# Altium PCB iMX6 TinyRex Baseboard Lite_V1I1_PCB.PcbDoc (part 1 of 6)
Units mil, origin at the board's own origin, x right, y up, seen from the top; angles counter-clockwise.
Board outline 3149.61 x 3543.31 mil, 6 copper layers (L1, L2, L3, L4 (PWR), L5, L6), stack 60.634 mil thick; 385 components, 309 nets, 1566 pads, 914 vias.
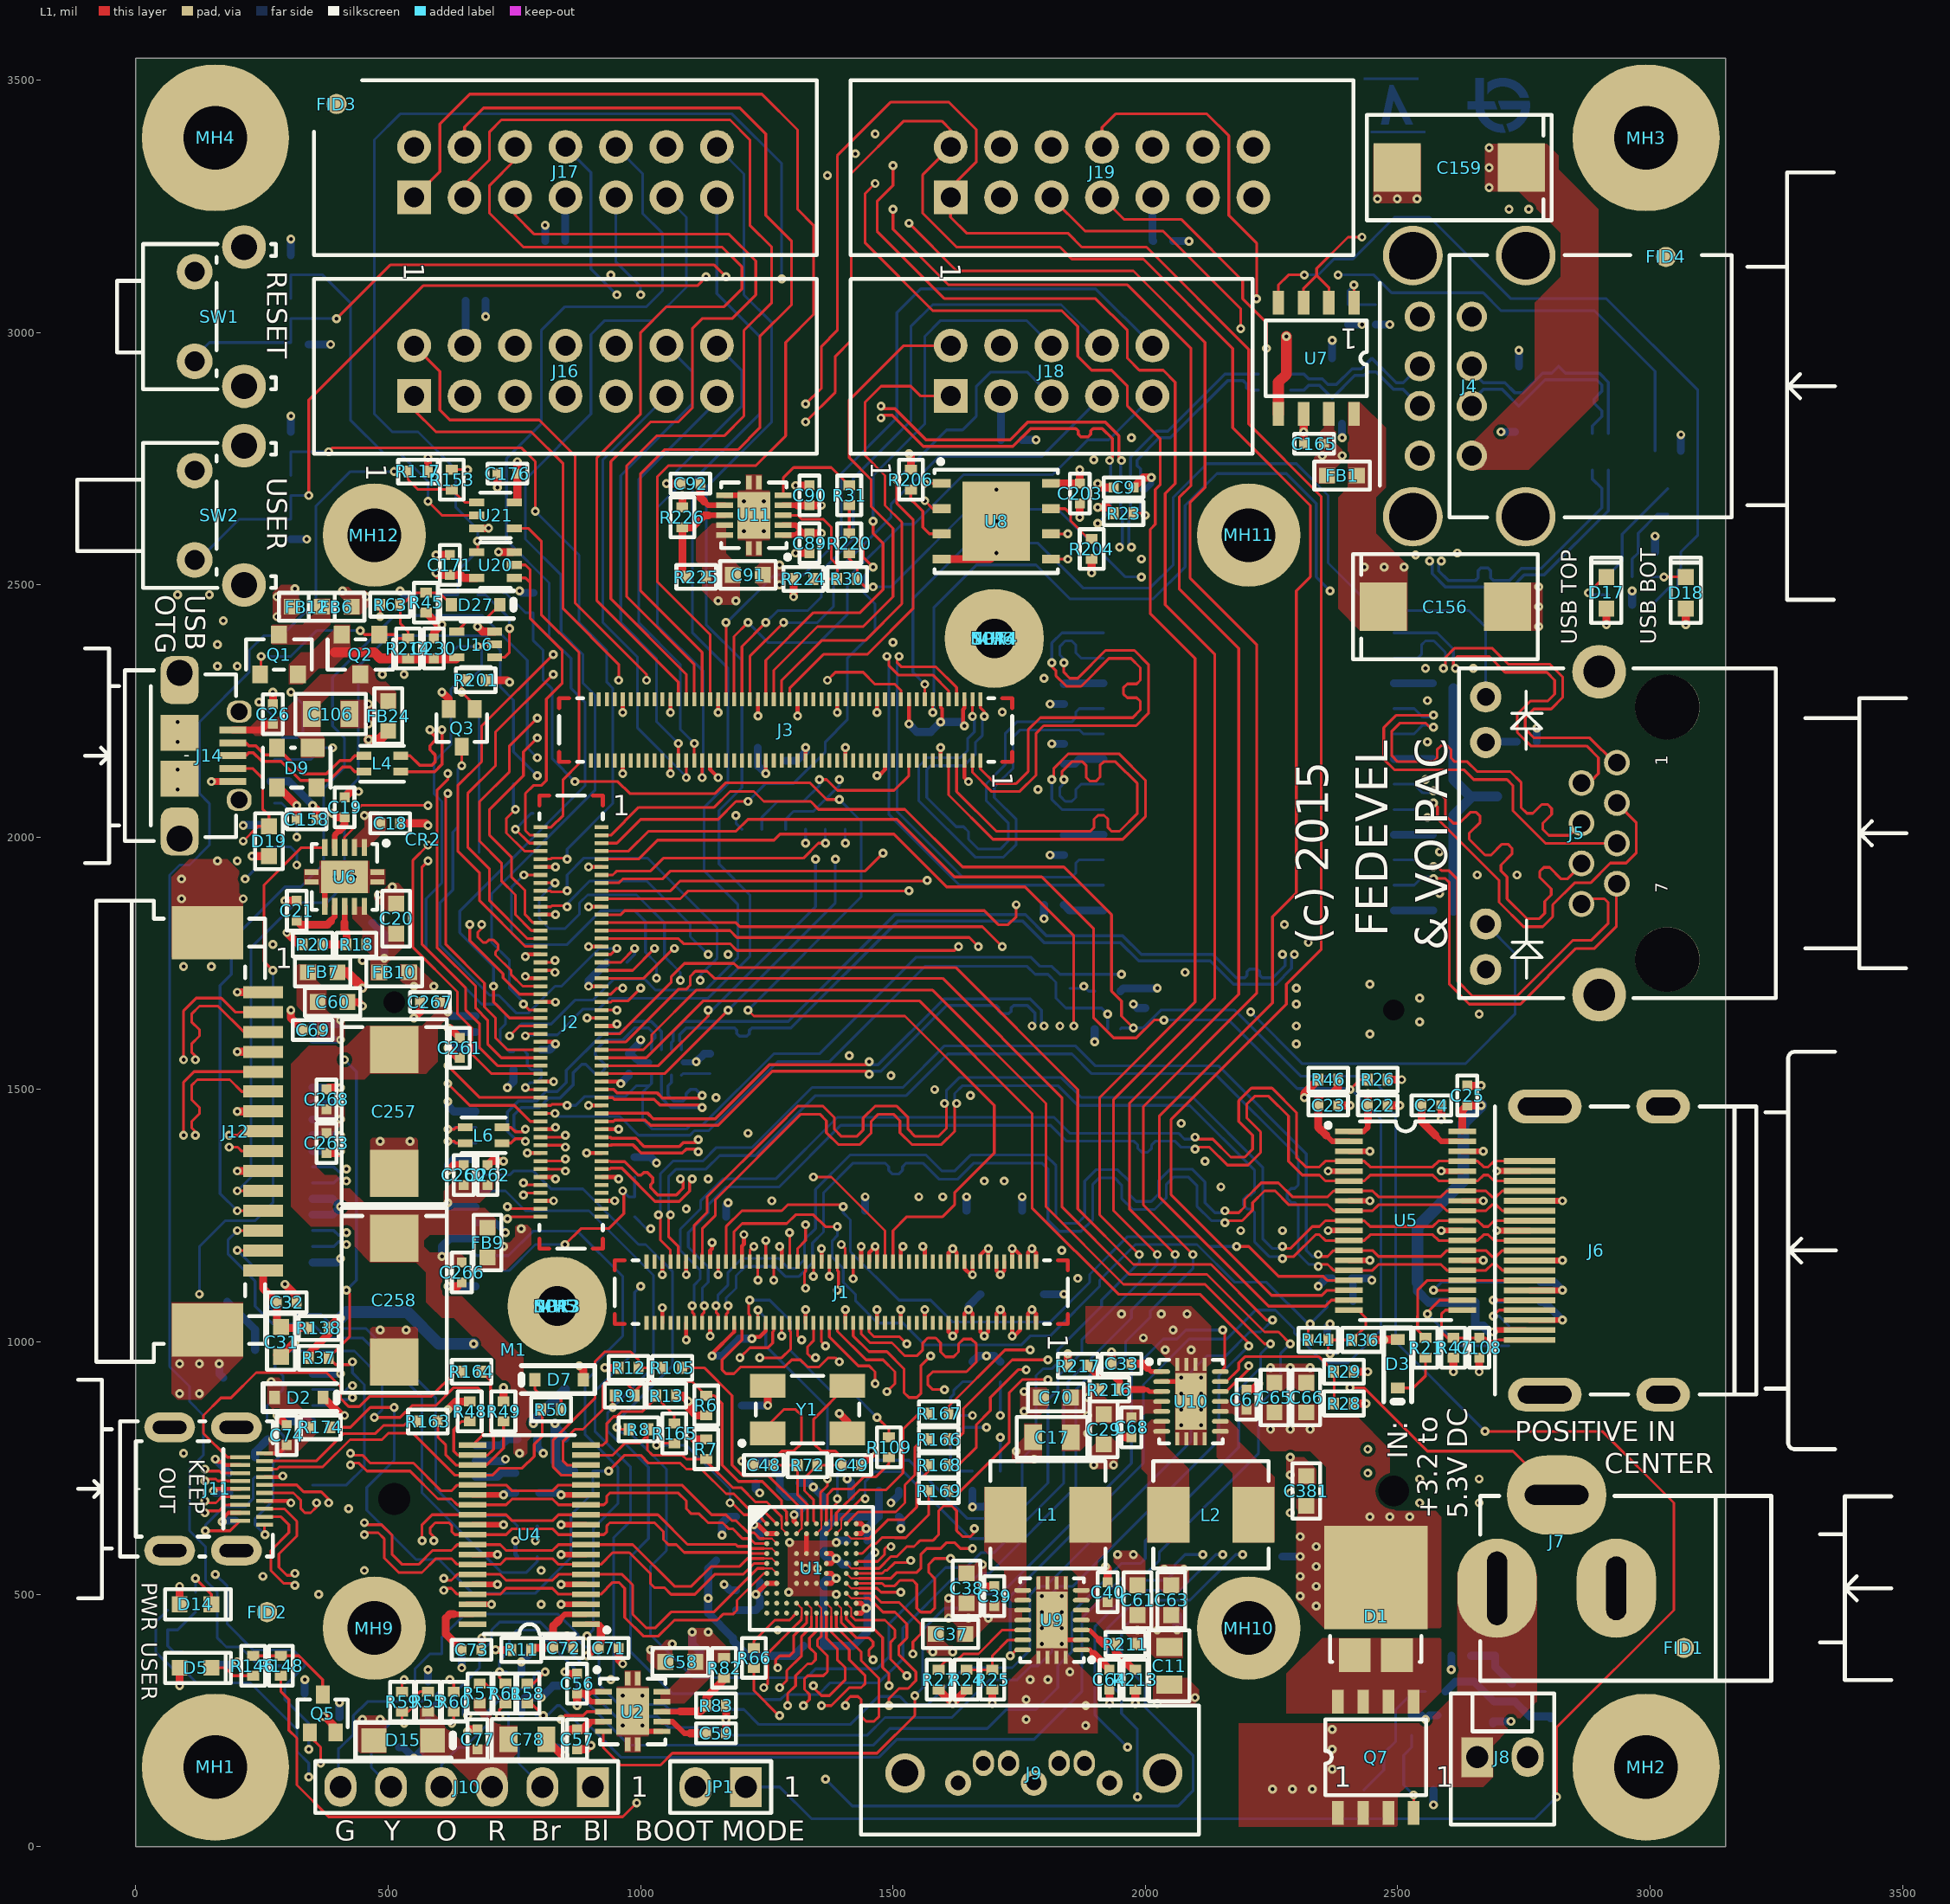
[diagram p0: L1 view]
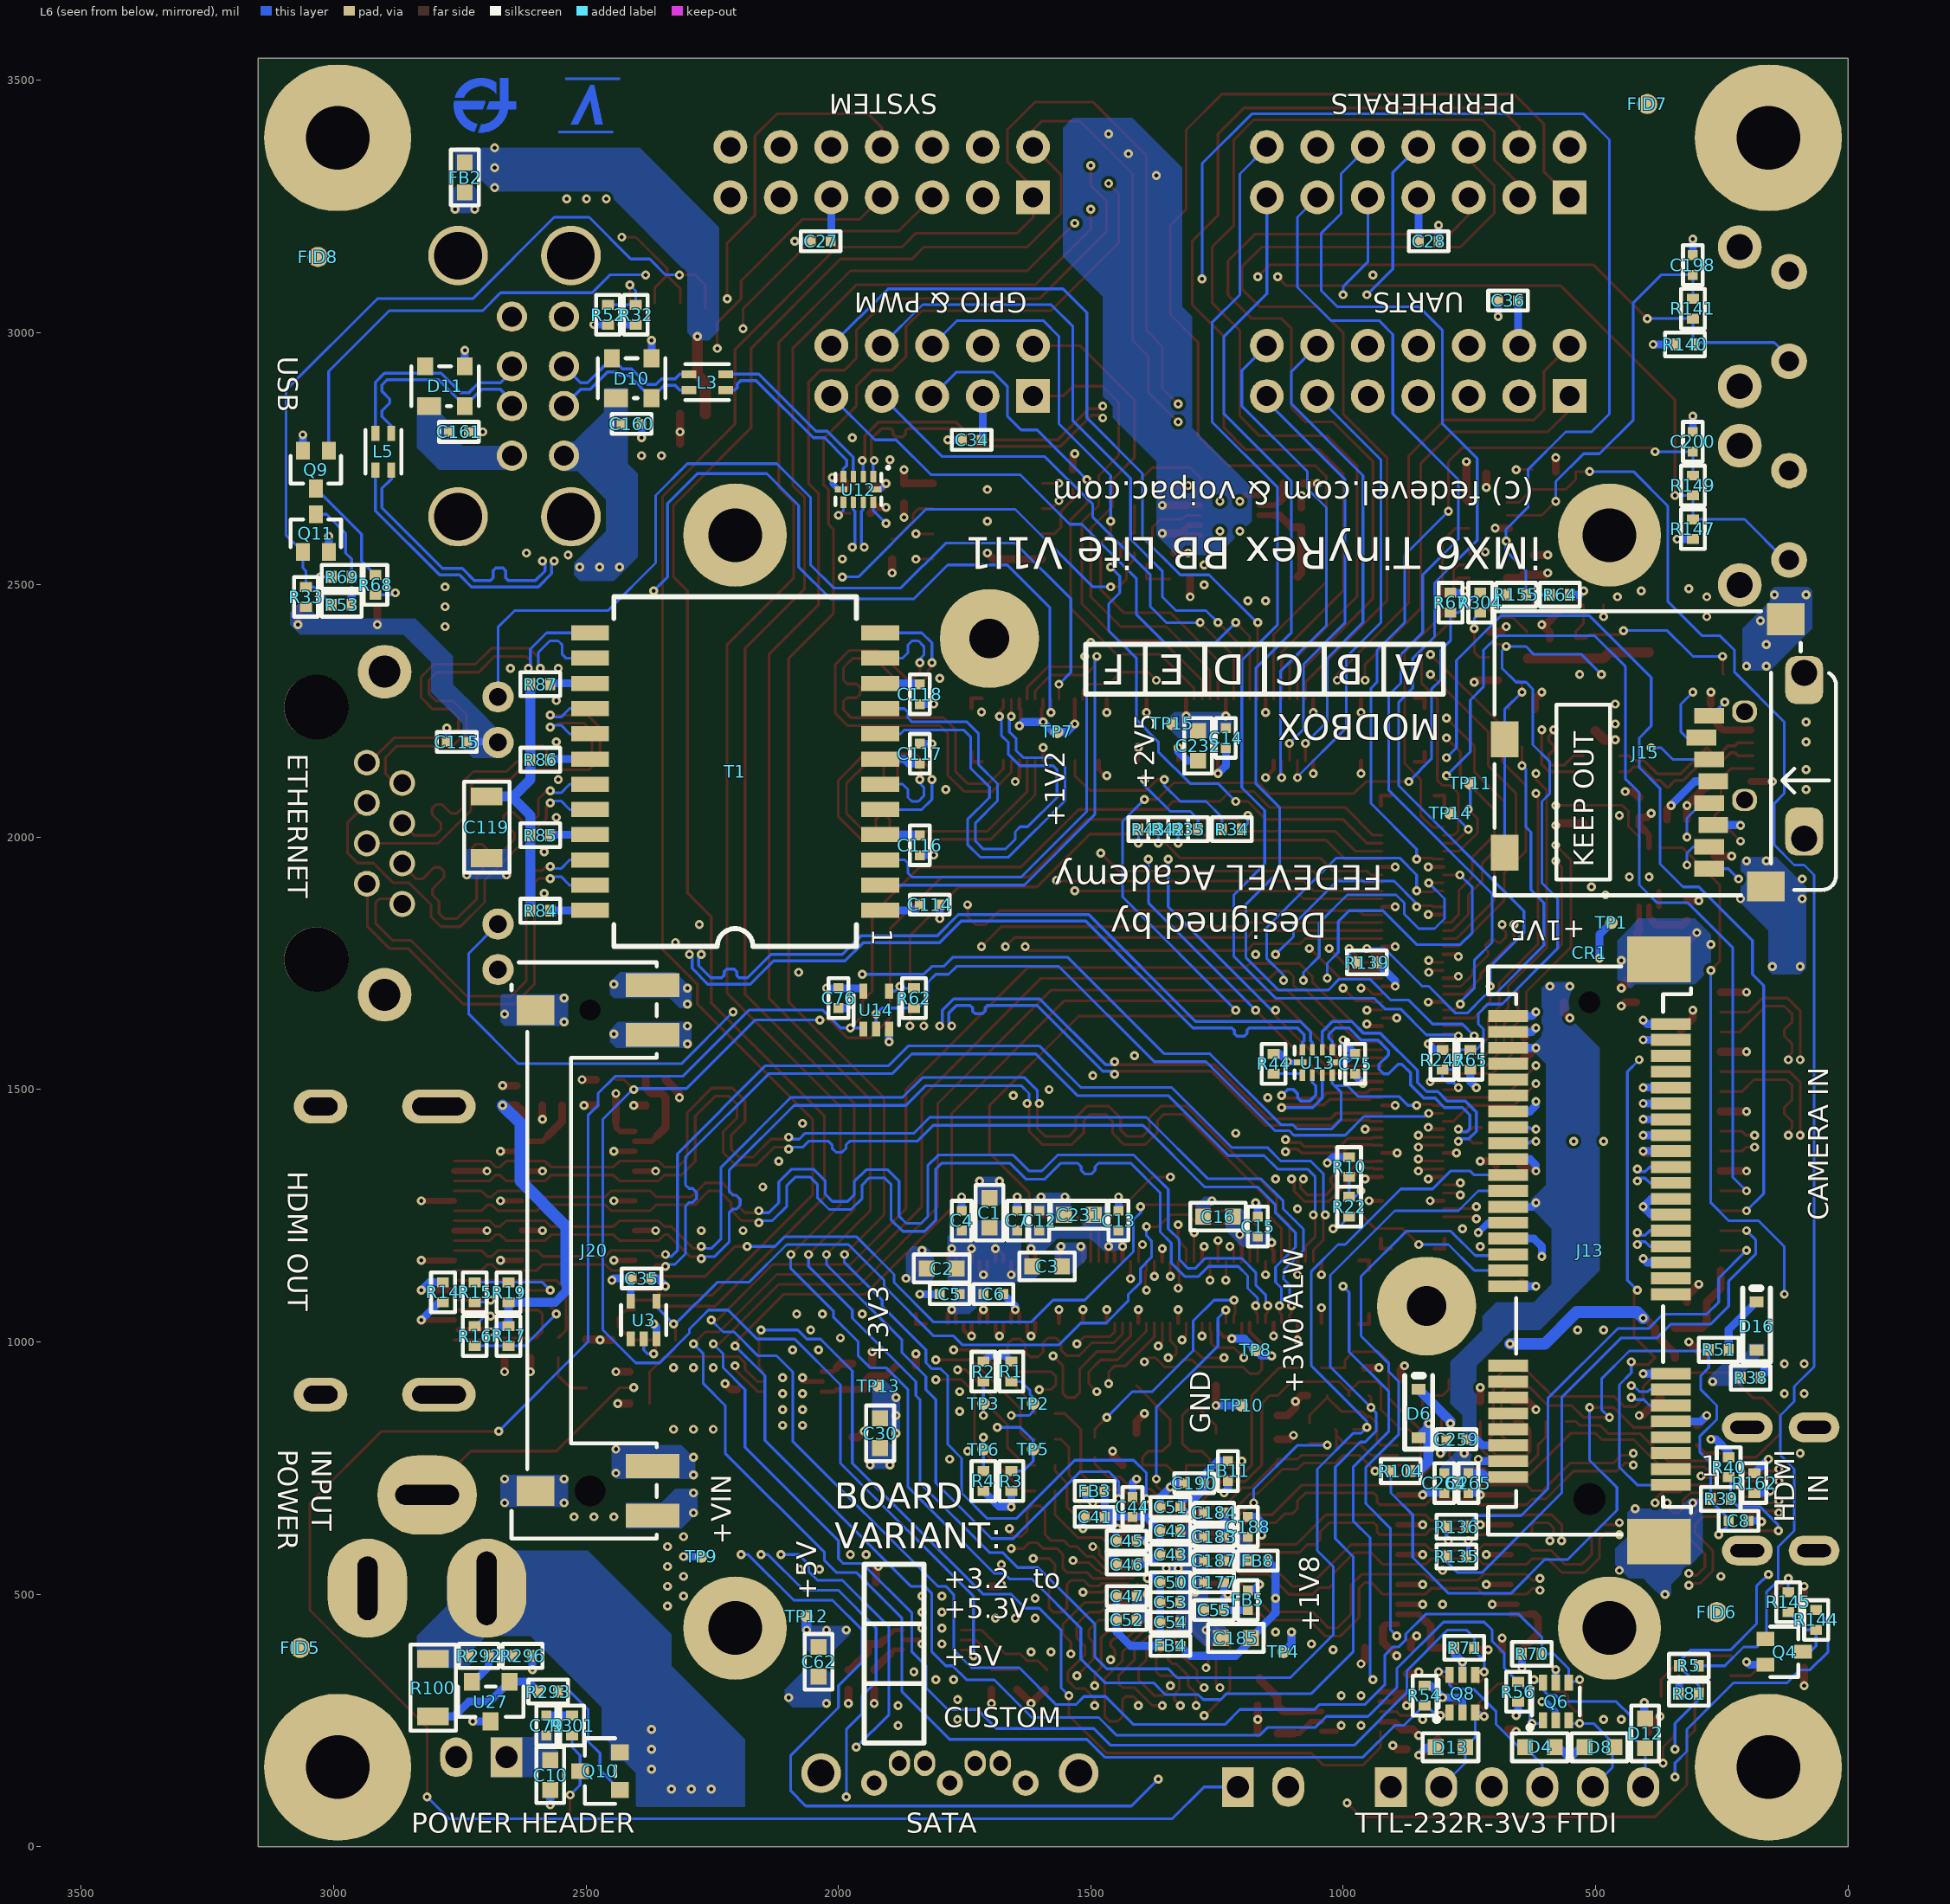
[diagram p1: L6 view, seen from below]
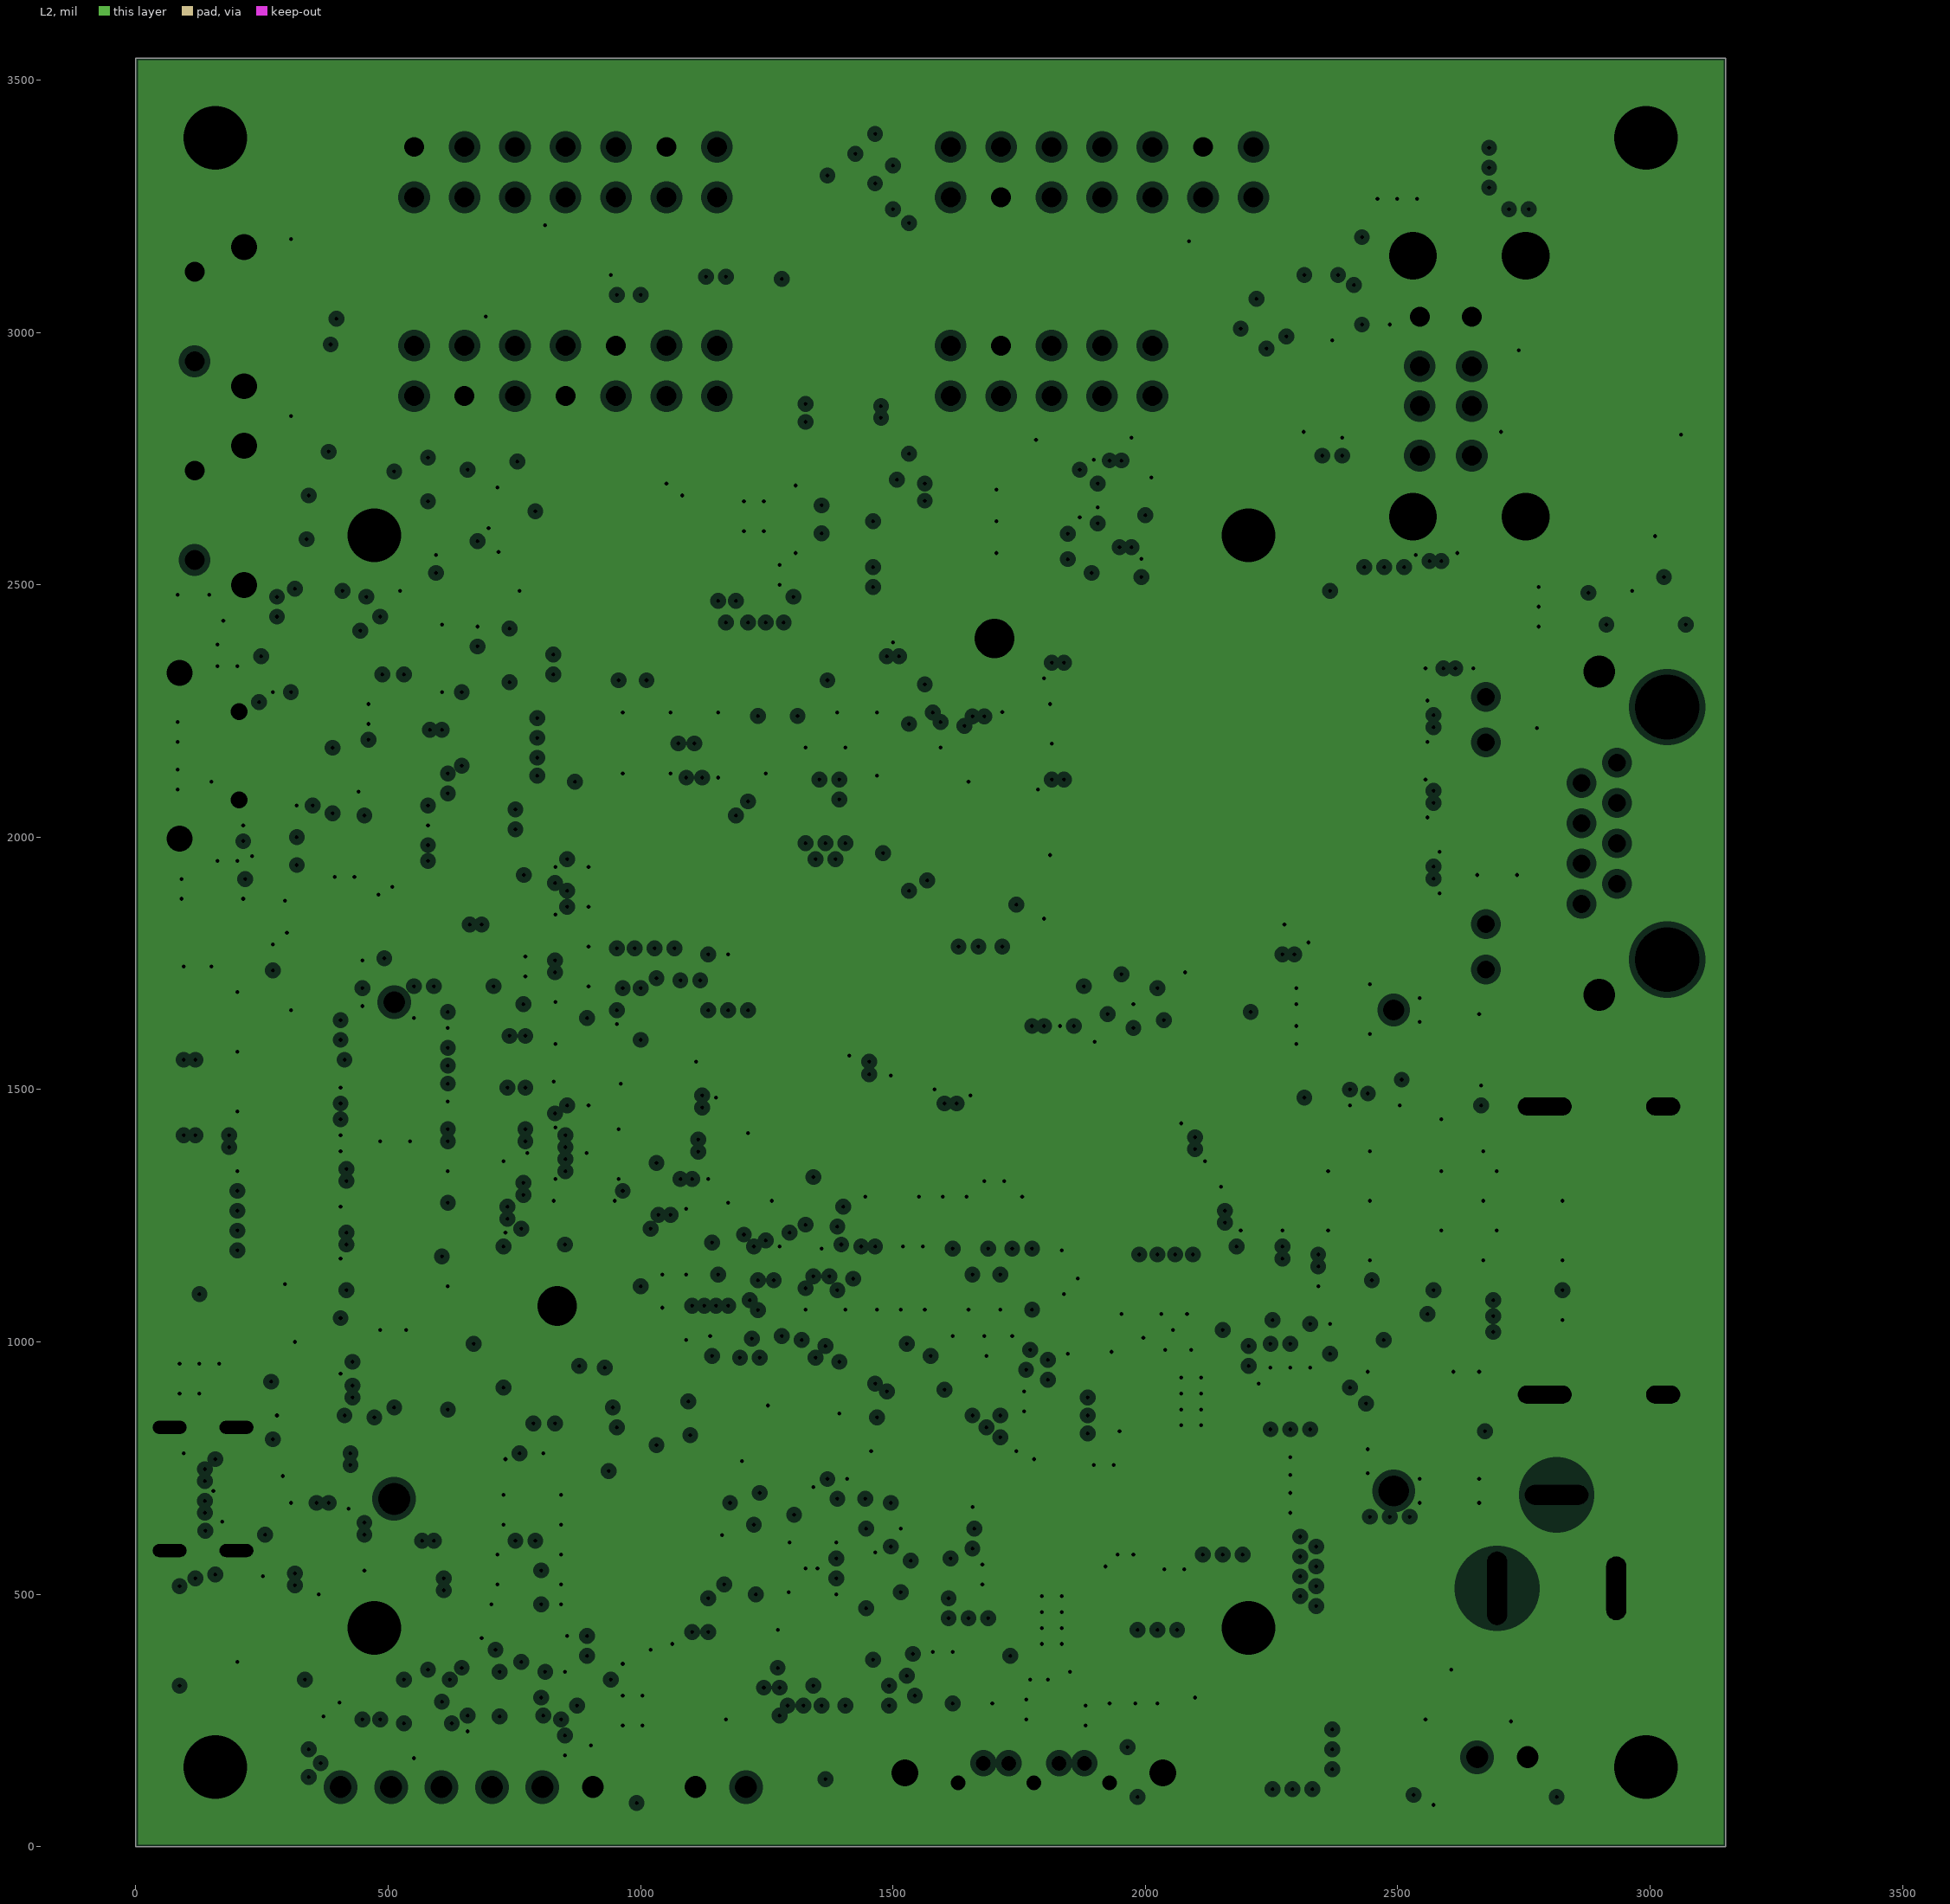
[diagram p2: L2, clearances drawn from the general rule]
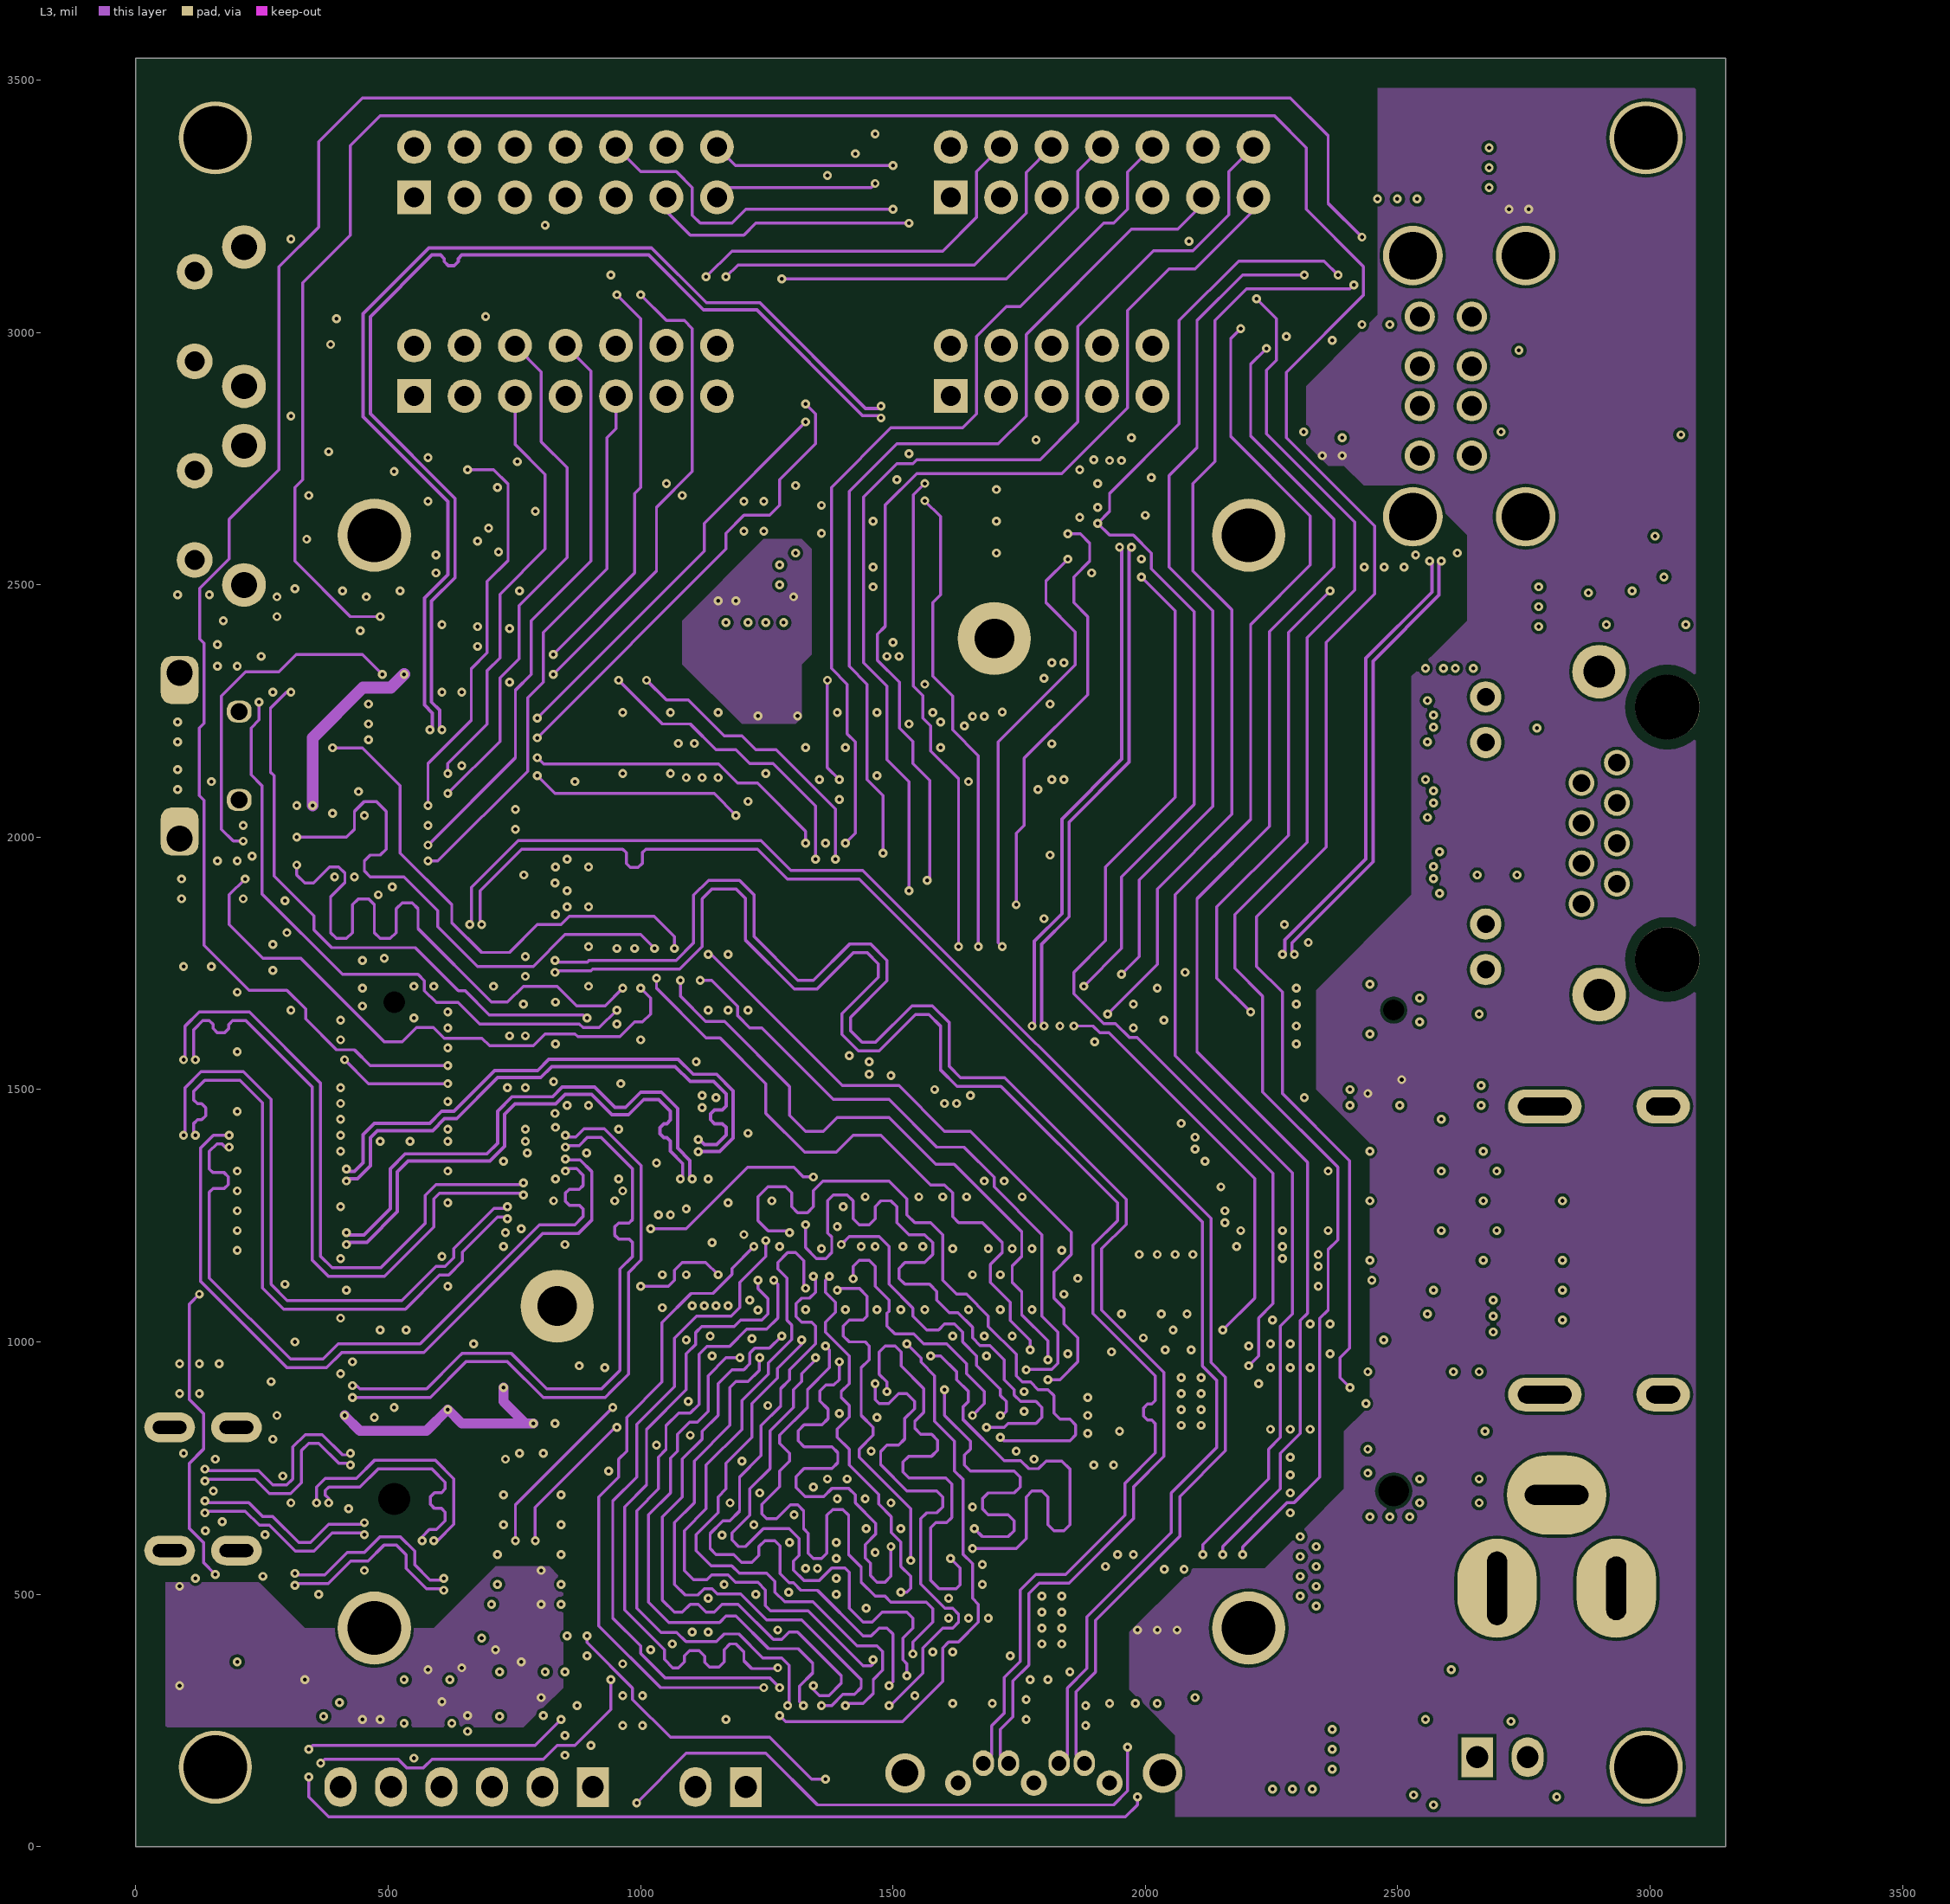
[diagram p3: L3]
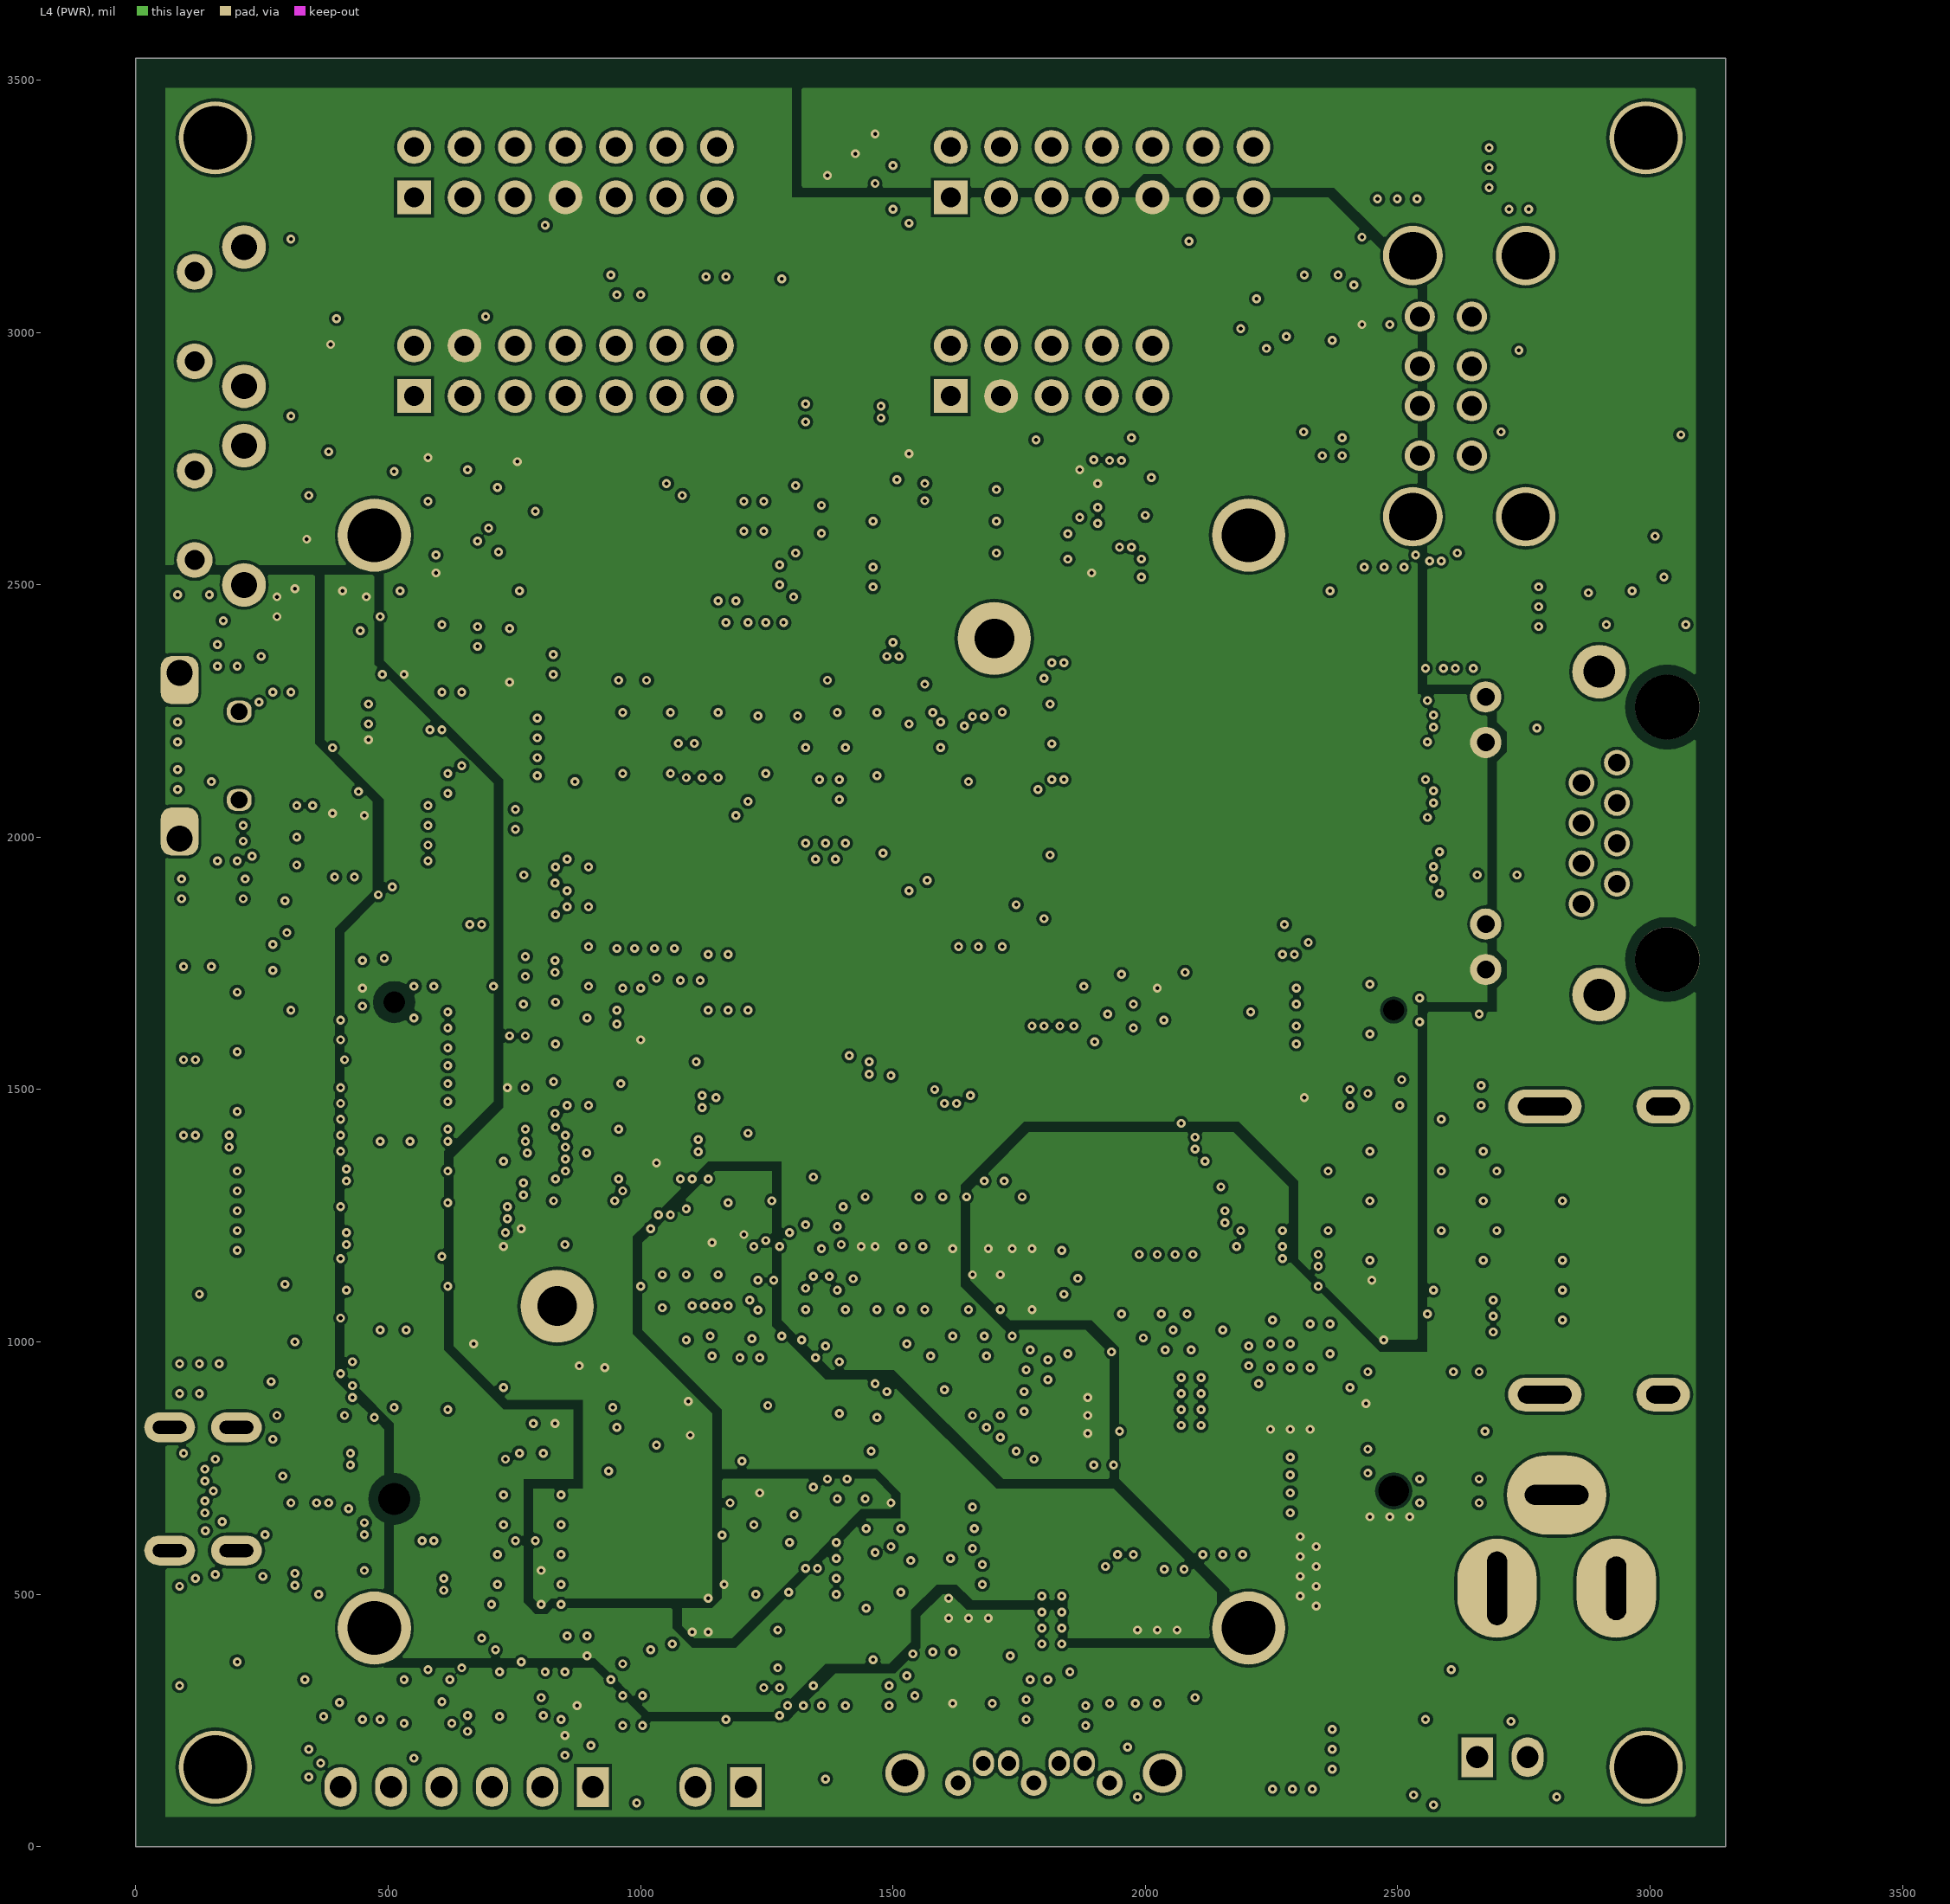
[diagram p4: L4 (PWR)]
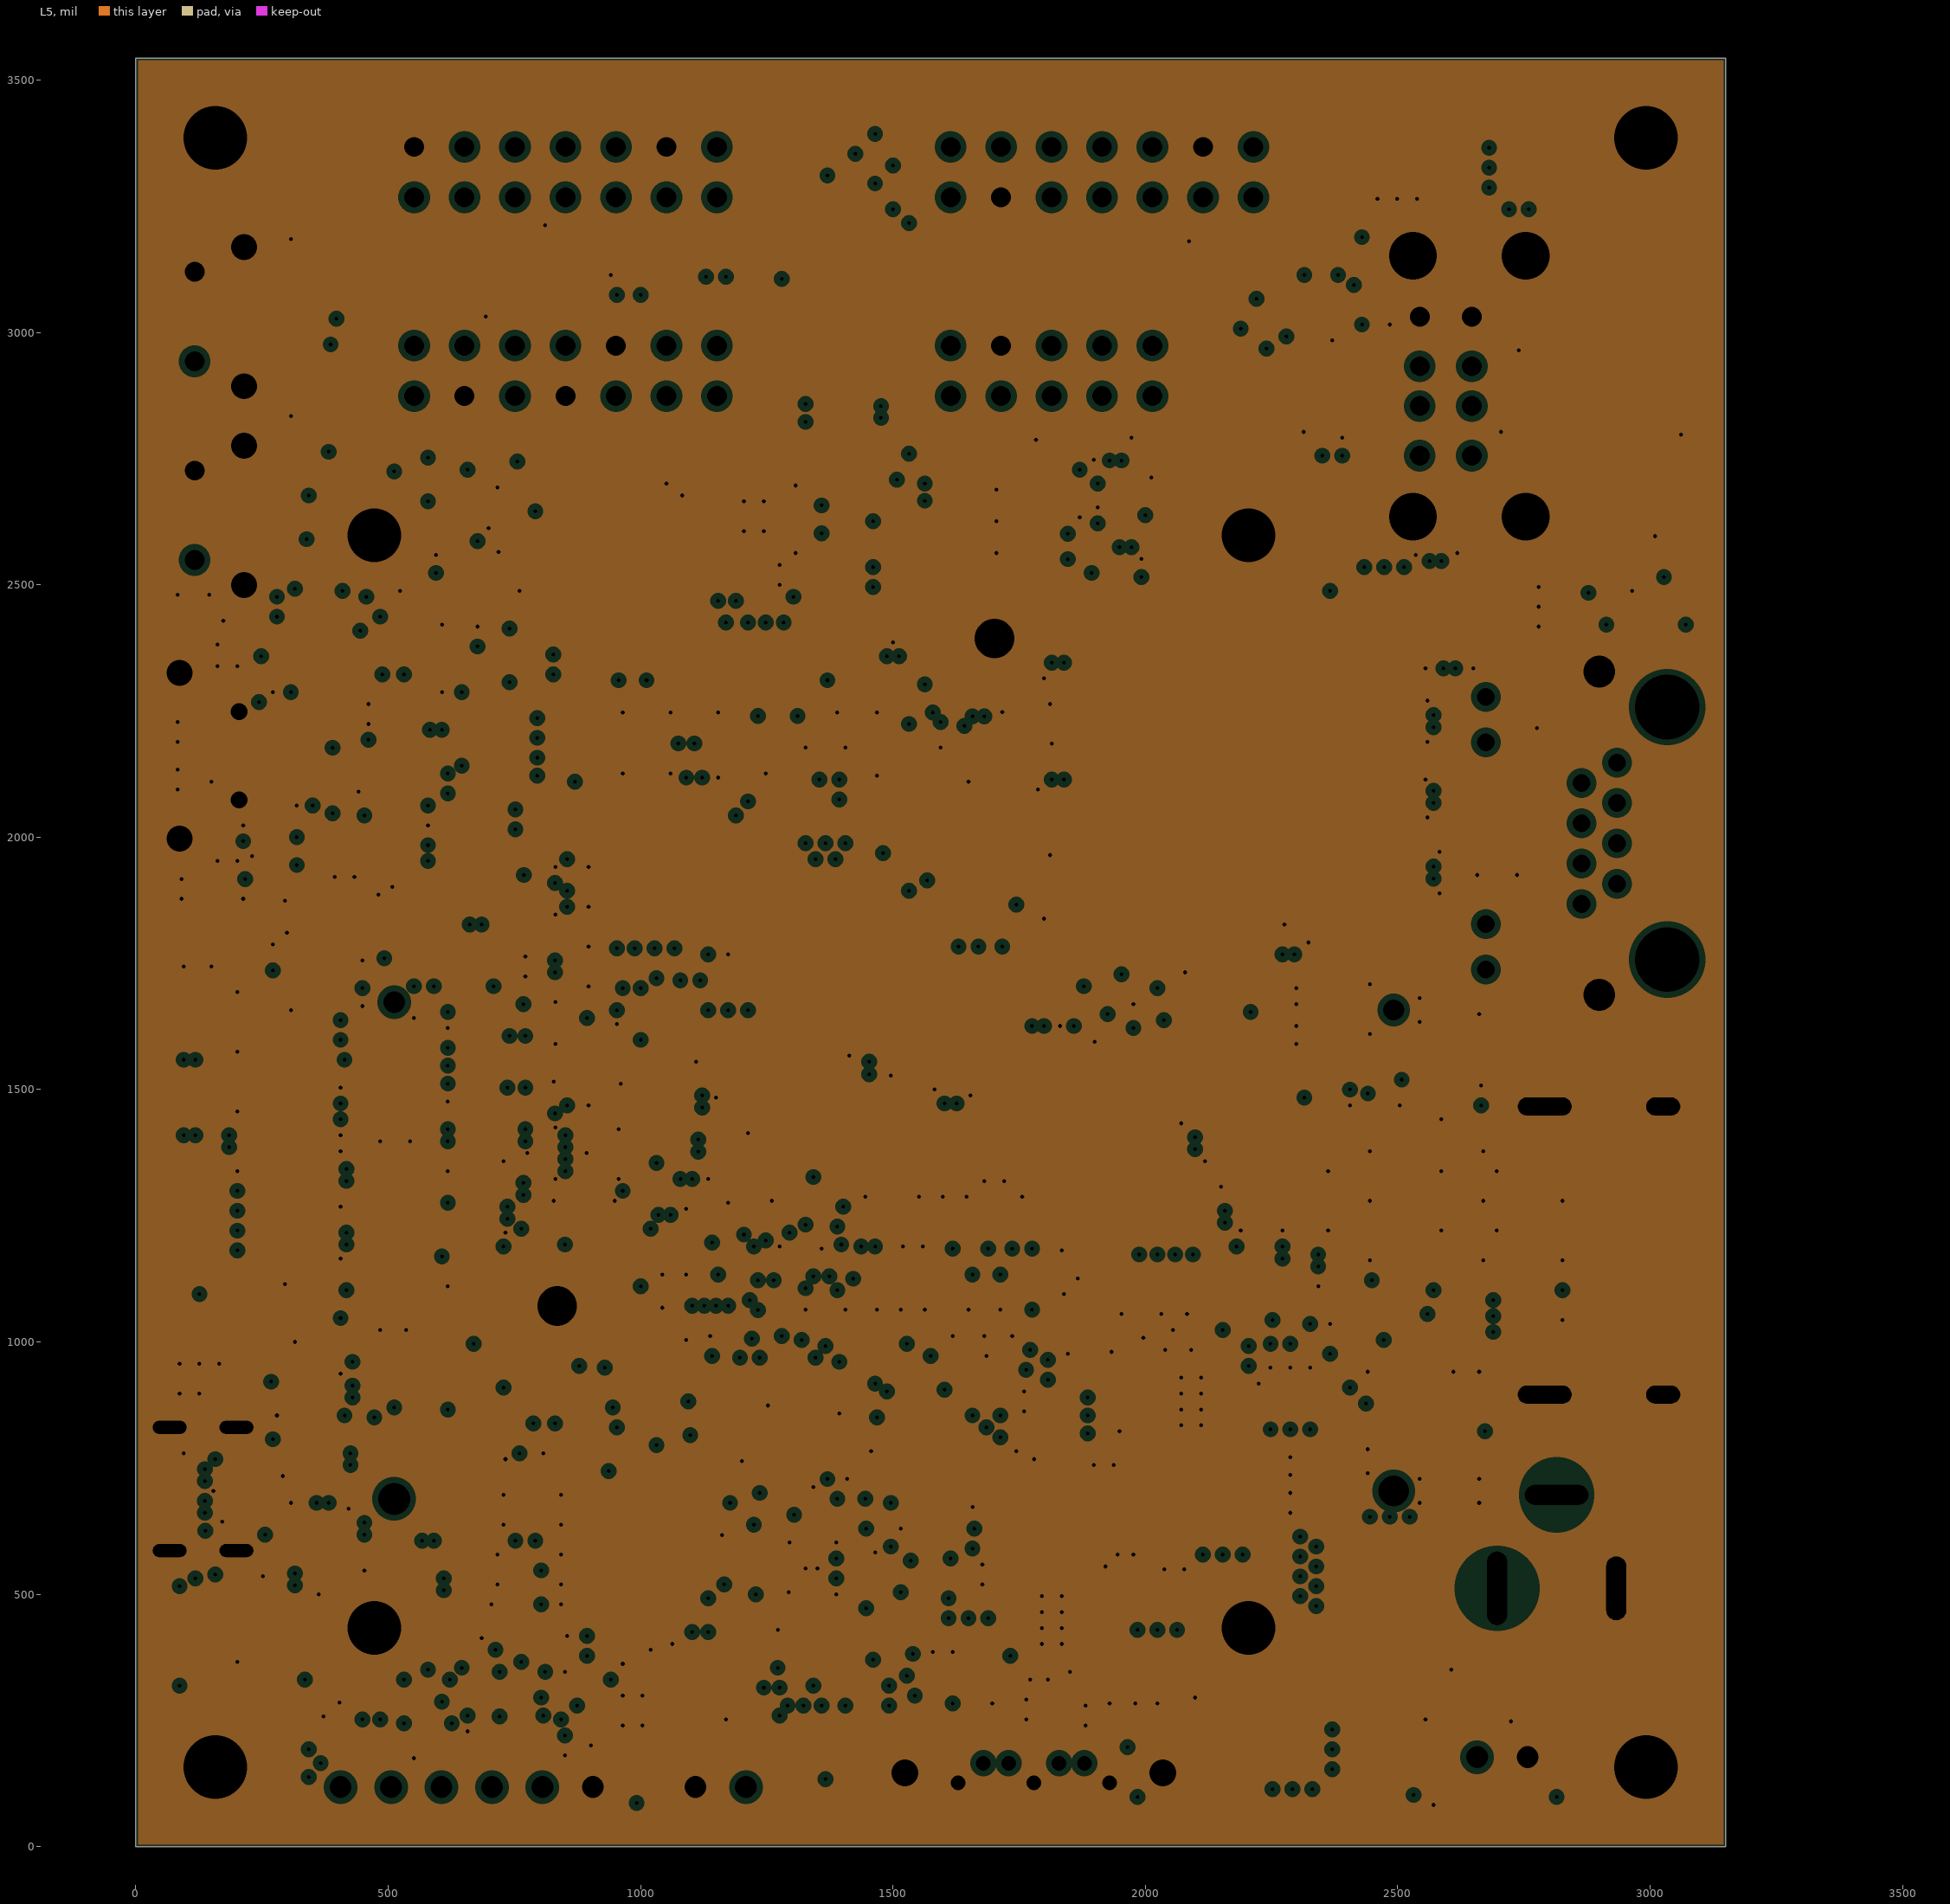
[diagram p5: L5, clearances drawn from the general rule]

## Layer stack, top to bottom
Top Solder: solder mask 0.4, Solder Resist, Dk 3.5
L1: signal copper 1.252
Dielectric1: core 4.64, DE 104 ML, Dk 4.3
L2: plane copper 0.685, net GND
Dielectric2: prepreg 5.5, DE 104 ML, Dk 3.95
L3: signal copper 0.685
Dielectric3: core 35.11, DE 104 ML, Dk 4.45
L4 (PWR): signal copper 0.685
Dielectric4: prepreg 5.5, DE 104 ML, Dk 3.95
L5: plane copper 0.685, net GND
Dielectric5: core 4.64, DE 104 ML, Dk 4.3
L6: signal copper 1.252
Bottom Solder: solder mask 0.4, Solder Resist, Dk 3.5

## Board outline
0,0 3149.61,0 3149.61,3543.31 0,3543.31 0,0

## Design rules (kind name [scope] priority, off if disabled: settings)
Clearance "Clearance Non Plated Holes" [InPadClass('NPTH')] p1: gap=19.68
Clearance "Pad Clearance" [IsPad vs IsPad] p2: gap=7.86
Clearance "CSI chip clearance" [WithinRoom('CSI') and OnLayer('L1')] p3: gap=2.95
Clearance "+VIN-L6 to GND pads" [InNamedPolygon('+VIN-L6') vs ispad] p4: gap=15.75
Clearance "Inners tracks" [IsTrack and (Layer = 'L3') and not(InNetClass('DIFF100') or InNetClass('DIFF90')) vs IsTrack] p5: gap=9.84
Clearance "Poly PWR to Via" [IsRegion AND OnLayer('L4 (PWR)') vs IsVia] p6: gap=5.91
Clearance "Poly to Poly" [IsRegion AND OnLayer('L4 (PWR)') vs IsRegion] p7: gap=15.75
Clearance [All] p8: gap=5.91
ComponentClearance "3D model Module" [InComponent('M1') vs InComponent('J1') or InComponent('J2') or InComponent('J3') or InComponent('SCR3') or InComponent('SCR4') or InComponent('SPA3') or InComponent('SPA4') or InComponent('NUT3') or InComponent('NUT4')] p1: gap=0 collisioncheckmode=3 verticalgap=0 showdistances=FALSE
ComponentClearance "MH5 to module mounting" [InComponent('MH5') vs InComponent('SCR3') or InComponent('SPA3')] p2: gap=0 collisioncheckmode=3 verticalgap=0 showdistances=FALSE
ComponentClearance "MH6 to module mounting" [InComponent('MH6') vs InComponent('SCR4') or InComponent('SPA4')] p3: gap=0 collisioncheckmode=3 verticalgap=0 showdistances=FALSE
ComponentClearance "SCR3 to module mounting" [InComponent('SCR3') vs InComponent('SPA3') or InComponent('NUT3')] p4: gap=0 collisioncheckmode=3 verticalgap=0 showdistances=FALSE
ComponentClearance "SCR4 to module mounting" [InComponent('SCR4') vs InComponent('SPA4') or InComponent('NUT4')] p5: gap=0 collisioncheckmode=3 verticalgap=0 showdistances=FALSE
ComponentClearance "PCIe card module to mounting" [InComponent('CR1') vs InComponent('J13') or InComponent('J20')] p6: gap=0 collisioncheckmode=3 verticalgap=0 showdistances=FALSE
ComponentClearance "SD Card model to SD slot" [InComponent('CR2') vs InComponent('J15')] p7: gap=0 collisioncheckmode=3 verticalgap=0 showdistances=FALSE
ComponentClearance "FID1 to J7" [InComponent('FID1') vs InComponent('J7')] p8: gap=0 collisioncheckmode=3 verticalgap=0 showdistances=FALSE
ComponentClearance "FID3 to J17" [InComponent('FID3') vs InComponent('J17')] p9: gap=0 collisioncheckmode=3 verticalgap=0 showdistances=FALSE
ComponentClearance "USB OTG power selection" [InComponent('FB12') vs InComponent('FB6')] p10: gap=0 collisioncheckmode=3 verticalgap=0 showdistances=FALSE
ComponentClearance "PIXCLOCK series resistors" [InComponent('R42') vs InComponent('R35') or InComponent('R43')] p11: gap=0 collisioncheckmode=3 verticalgap=0 showdistances=FALSE
ComponentClearance [All] p12: gap=7.87 collisioncheckmode=3 verticalgap=7.87 showdistances=FALSE
DiffPairsRouting DiffPair_DIFF100DiffPairsRouting [InDifferentialPairClass('DIFF100')] p1: maxlimit=11.09 minlimit=10 mostfreqgap=11.09 toplayer_mingap=10.51 toplayer_maxgap=10.51 toplayer_prefgap=10.51 toplayer_minwidth=3.94 toplayer_maxwidth=5.4 toplayer_prefwidth=5.4 midlayer1_mingap=11.09 midlayer1_minwidth=6 midlayer1_maxwidth=6 midlayer1_prefwidth=6 midlayer2_maxgap=10 midlayer2_prefgap=10 midlayer2_minwidth=10 midlayer2_maxwidth=10 midlayer2_prefwidth=10 bottomlayer_mingap=10.51 bottomlayer_maxgap=10.51 bottomlayer_prefgap=10.51 bottomlayer_minwidth=5.4 bottomlayer_maxwidth=5.4 bottomlayer_prefwidth=5.4 maxuncoupledlength=640
DiffPairsRouting DiffPair_DIFF90DiffPairsRouting [InDifferentialPairClass('DIFF90')] p2: maxlimit=10 minlimit=6.99 mostfreqgap=10 toplayer_maxgap=6.99 toplayer_prefgap=6.99 toplayer_minwidth=6 toplayer_maxwidth=6 toplayer_prefwidth=6 midlayer1_mingap=7.6 midlayer1_maxgap=7.6 midlayer1_prefgap=7.6 midlayer1_minwidth=6.7 midlayer1_maxwidth=6.7 midlayer1_prefwidth=6.7 midlayer2_mingap=10 midlayer2_minwidth=10 midlayer2_maxwidth=10 midlayer2_prefwidth=10 bottomlayer_maxgap=6.99 bottomlayer_prefgap=6.99 bottomlayer_minwidth=6 bottomlayer_maxwidth=6 bottomlayer_prefwidth=6 maxuncoupledlength=450
DiffPairsRouting [All] p3: maxlimit=7.87 minlimit=7.87 mostfreqgap=7.87 toplayer_minwidth=15 toplayer_maxwidth=15 toplayer_prefwidth=15 midlayer1_minwidth=15 midlayer1_maxwidth=15 midlayer1_prefwidth=15 midlayer2_minwidth=15 midlayer2_maxwidth=15 midlayer2_prefwidth=15 bottomlayer_minwidth=15 bottomlayer_maxwidth=15 bottomlayer_prefwidth=15 maxuncoupledlength=500
Height [All] p1: minheight=-314.96 maxheight=1000 prefheight=500
HoleSize [All] p1: absolutevalues=TRUE maxlimit=393.7 minlimit=7.87 maxpercent=80.000 minpercent=20.000
HoleToHoleClearance [All] p1: gap=11.81 allowstackedmicrovias=TRUE
MatchedLengths DiffPair_DIFF100MatchedLengths [InDifferentialPairClass('DIFF100')] p1: tolerance=5 checknetsindiffpair=TRUE checkdiffpairvsdiffpair=FALSE checkothers=FALSE
MatchedLengths DiffPair_DIFF90MatchedLengths [InDifferentialPairClass('DIFF90')] p2: tolerance=5 checknetsindiffpair=TRUE checkdiffpairvsdiffpair=FALSE checkothers=FALSE
MinimumSolderMaskSliver [All] p1: minsoldermaskwidth=3.94
PlaneClearance [All] p1: clearance=11.81
PlaneConnect "GND to J7" [Incomponent('J7')] p1: planeconnectstyle=Relief reliefexpansion=19.68 reliefentries=4 reliefconductorwidth=86.61 reliefairgap=11.81
PlaneConnect "GND to J7_1" [Incomponent('J8')] p2: planeconnectstyle=Relief reliefexpansion=19.68 reliefentries=4 reliefconductorwidth=47.24 reliefairgap=11.81
PlaneConnect "GND to MH" [Incomponent('MH1') or Incomponent('MH2') or Incomponent('MH3') or Incomponent('MH4') or Incomponent('MH5') or Incomponent('MH6') or Incomponent('MH9') or Incomponent('MH10') or Incomponent('MH11') or Incomponent('MH12')] p3: planeconnectstyle=Direct reliefexpansion=20 reliefentries=4 reliefconductorwidth=10 reliefairgap=10
PlaneConnect "GND to PAD" [(InNet('GND') and IsPad)] p4: planeconnectstyle=Relief reliefexpansion=11.81 reliefentries=4 reliefconductorwidth=19.68 reliefairgap=7.87
PlaneConnect [All] p5: planeconnectstyle=Direct reliefexpansion=7.87 reliefentries=4 reliefconductorwidth=11.81 reliefairgap=7.87
PolygonConnect [All] p1: connectstyle=Direct reliefconductorwidth=10 reliefentries=4 polygonreliefangle="90 Angle" airgapwidth=10
RoomDefinition CSI [InComponentClass('CSI')] p1: confinementstyle=ConfineIn formatcopy=TRUE lockcomponents=FALSE outline 1208.66,681.1 1488.19,681.1 1488.19,409.45 1208.66,409.45
RoutingVias [All] p1: holewidth=7.87 width=17.72 viastyle="Through Hole" minholewidth=7.87 minwidth=17.72 maxholewidth=19.68 maxwidth=39.37
SilkToSilkClearance [All] p1: silktosilkclearance=3.94
SilkToSolderMaskClearance SilkscreenOverComponentPads [IsPad] p1: minsilkscreentomaskgap=3.94 clearancetoexposedcopper=TRUE
SolderMaskExpansion [All] p1: expansion=4
UnpouredPolygon [All] p1: allowunpoured=FALSE
Width DiffPair_DIFF100Width [InDifferentialPairClass('DIFF100')] p1: maxlimit=10 minlimit=3.94 preferedwidth=10 toplayer_maxwidth=5.4 toplayer_prefwidth=5.4 midlayer1_minwidth=6 midlayer1_maxwidth=6 midlayer1_prefwidth=6 midlayer2_minwidth=10 bottomlayer_minwidth=5.4 bottomlayer_maxwidth=5.4 bottomlayer_prefwidth=5.4 minimp=50.000000 maximp=50.000000 favimp=50.000000
Width DiffPair_DIFF90Width [InDifferentialPairClass('DIFF90')] p2: maxlimit=10 minlimit=6 preferedwidth=10 toplayer_maxwidth=6 toplayer_prefwidth=6 midlayer1_minwidth=6.7 midlayer1_maxwidth=6.7 midlayer1_prefwidth=6.7 midlayer2_minwidth=10 bottomlayer_maxwidth=6 bottomlayer_prefwidth=6 minimp=50.000000 maximp=50.000000 favimp=50.000000
Width "Width Power" [InNet('+VIN') OR InNet('+5V') OR InNet('+3V3') OR InNet('+1V5') OR InNet('+1V8') OR InNet('+2V5')] p3: maxlimit=157.48 minlimit=7.09 preferedwidth=15.75
Width "Width Ground" [InNet('GND')] p4: maxlimit=1574.8 minlimit=7.09 preferedwidth=15.75
Width [All] p5: maxlimit=78.74 minlimit=3.94 preferedwidth=9.84 toplayer_prefwidth=6.3 midlayer1_minwidth=5.9 midlayer1_prefwidth=8.27 midlayer2_minwidth=9.84 bottomlayer_minwidth=5.4 bottomlayer_prefwidth=6.3 minimp=50.000000 maximp=50.000000 favimp=50.000000
19 further rules are at their usual default settings.

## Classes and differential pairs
net class UART4: UART4_RXD UART4_TXD
net class FLEXCAN1: FLEXCAN1_RX FLEXCAN1_TX
net class GPIO_OR_PWM: GPIO_OR_PWM_1 GPIO_OR_PWM_2
net class PCIE: PCIE_CLK_N PCIE_CLK_P PCIE_RX_N PCIE_RX_P PCIE_TX_N PCIE_TX_P PCIE_WAKE
net class I2C1: I2C1_SCL I2C1_SDA
net class SPI2: CSPI2_CLK CSPI2_CS0 CSPI2_CS1 CSPI2_MISO CSPI2_MOSI
net class SPI1: CSPI1_CLK CSPI1_CS0 CSPI1_MISO CSPI1_MOSI
net class I2C3: I2C3_SCL I2C3_SDA
net class I2C2: I2C2_SCL I2C2_SDA
net class GPIO: CPU_GPIO0 CPU_GPIO0_R CPU_GPIO1
net class GPIO_HDR: CPU_GPIO2 CPU_GPIO3 CPU_GPIO4 CPU_GPIO5 CPU_GPIO6 CPU_GPIO7 GPIO_OR_PWM_3 GPIO_OR_PWM_4
net class AUD4: AUD4_CLK_R AUD4_RXD_R AUD4_TXC_R AUD4_TXFS_R
net class VID_IN_CSI0: HDMI_HPA_A VID_IN_CSI0_D0 VID_IN_CSI0_D1 VID_IN_CSI0_D2 VID_IN_CSI0_D3 VID_IN_CSI0_D4 VID_IN_CSI0_D5 VID_IN_CSI0_D6 VID_IN_CSI0_D7 VID_IN_CSI0_D8 VID_IN_CSI0_D9 VID_IN_CSI0_D10 VID_IN_CSI0_D11 VID_IN_CSI0_D12 VID_IN_CSI0_D13 VID_IN_CSI0_D14 VID_IN_CSI0_D15 VID_IN_CSI0_D16 VID_IN_CSI0_D17 VID_IN_CSI0_D18 VID_IN_CSI0_D19 VID_IN_CSI0_DE VID_IN_CSI0_HS VID_IN_CSI0_INT VID_IN_CSI0_INT_R VID_IN_CSI0_PIXCLK VID_IN_CSI0_PIXCLK_R VID_IN_CSI0_RSTN VID_IN_CSI0_VS
net class UART5: UART5_RXD UART5_TXD
net class UART3: UART3_CTS UART3_RTS UART3_RXD UART3_TXD
net class MIPI_CSI: CSI1_GPIO CSI1_GPIO_R CSI1_PIXCLK CSI1_PIXCLK_R CSI_CLK0_N CSI_CLK0_P CSI_D0_N CSI_D0_P CSI_D1_N CSI_D1_P I2C2_CSI_SCL I2C2_CSI_SDA
net class HDMI_OUT: HDMI_OUT_CEC_CON HDMI_OUT_CEC_IN HDMI_OUT_CLK_N HDMI_OUT_CLK_P HDMI_OUT_D0_N HDMI_OUT_D0_P HDMI_OUT_D1_N HDMI_OUT_D1_P HDMI_OUT_D2_N HDMI_OUT_D2_P HDMI_OUT_HPD HDMI_OUT_HPD_CON HDMI_OUT_HPD_R HDMI_OUT_SCL_CON HDMI_OUT_SCL_CON_R HDMI_OUT_SDA_CON HDMI_OUT_SDA_CON_R
net class HDMI_IN: HDMI_IN_CEC_CON HDMI_IN_CEC_IN HDMI_IN_CLK_N HDMI_IN_CLK_P HDMI_IN_D0_N HDMI_IN_D0_P HDMI_IN_D1_N HDMI_IN_D1_P HDMI_IN_D2_N HDMI_IN_D2_P HDMI_IN_HPD HDMI_IN_HPD_CON HDMI_IN_SCL_CON HDMI_IN_SCL_CON_R HDMI_IN_SDA_CON HDMI_IN_SDA_CON_R I2C2_DDC_SCL I2C2_DDC_SDA
net class MX: MX0_N MX0_P MX1_N MX1_P MX2_N MX2_P MX3_N MX3_P
net class uSD: SD3_CD SD3_CLK SD3_CMD SD3_DATA0 SD3_DATA1 SD3_DATA2 SD3_DATA3 SD3_WP
net class UART2: UART2_RXD UART2_TXD
net class DIFF90: PCIE_RX_N PCIE_RX_P PCIE_TX_N PCIE_TX_P USB0_CON_N USB0_CON_P USB0_L_N USB0_L_P USB0_N USB0_P USB1_CON_N USB1_CON_P USB1_L_N USB1_L_P USB1_N USB1_P USB_MPCIE_CON_N USB_MPCIE_CON_P USB_MPCIE_N USB_MPCIE_P USB_OTG_CON_N USB_OTG_CON_P USB_OTG_N USB_OTG_P
net class DIFF100: CSI_CLK0_N CSI_CLK0_P CSI_D0_N CSI_D0_P CSI_D1_N CSI_D1_P HDMI_IN_CLK_N HDMI_IN_CLK_P HDMI_IN_D0_N HDMI_IN_D0_P HDMI_IN_D1_N HDMI_IN_D1_P HDMI_IN_D2_N HDMI_IN_D2_P HDMI_OUT_CLK_N HDMI_OUT_CLK_P HDMI_OUT_D0_N HDMI_OUT_D0_P HDMI_OUT_D1_N HDMI_OUT_D1_P HDMI_OUT_D2_N HDMI_OUT_D2_P MX0_N MX0_P MX1_N MX1_P MX2_N MX2_P MX3_N MX3_P PCIE_CLK_N PCIE_CLK_P SATA_RX_N SATA_RX_P SATA_TX_N SATA_TX_P TRD0_N TRD0_P TRD1_N TRD1_P TRD2_N TRD2_P TRD3_N TRD3_P
net class PHY: TRD0_N TRD0_P TRD1_N TRD1_P TRD2_N TRD2_P TRD3_N TRD3_P
net class SATA: SATA_RX_N SATA_RX_P SATA_TX_N SATA_TX_P
net class UART1: UART1_CTS UART1_CTS_FTDI UART1_RTS UART1_RTS_FTDI UART1_RXD UART1_RXD_FTDI UART1_TXD UART1_TXD_FTDI
net class USB0: USB0_CON_N USB0_CON_P USB0_ID USB0_L_N USB0_L_P USB0_N USB0_P USB_OTG_CON_N USB_OTG_CON_P USB_OTG_N USB_OTG_P
net class USB1: USB1_CON_N USB1_CON_P USB1_L_N USB1_L_P USB1_N USB1_P USB_MPCIE_CON_N USB_MPCIE_CON_P USB_MPCIE_N USB_MPCIE_P
differential pair class DIFF90: PCIE_RX PCIE_TX USB0 USB0_CON USB0_L USB1 USB1_CON USB1_L USB_MPCIE USB_MPCIE_CON USB_OTG USB_OTG_CON
differential pair class DIFF100: CSI_CLK0 CSI_D0 CSI_D1 HDMI_IN_CLK HDMI_IN_D0 HDMI_IN_D1 HDMI_IN_D2 HDMI_OUT_CLK HDMI_OUT_D0 HDMI_OUT_D1 HDMI_OUT_D2 MX0 MX1 MX2 MX3 PCIE_CLK SATA_RX SATA_TX TRD0 TRD1 TRD2 TRD3
pad class NPTH: J5-15 J5-16 J13-55 J13-56
differential pair PCIE_TX: +PCIE_TX_P -PCIE_TX_N
differential pair PCIE_RX: +PCIE_RX_P -PCIE_RX_N
differential pair PCIE_CLK: +PCIE_CLK_P -PCIE_CLK_N
differential pair USB_MPCIE: +USB_MPCIE_P -USB_MPCIE_N
differential pair USB_MPCIE_CON: +USB_MPCIE_CON_P -USB_MPCIE_CON_N
differential pair USB1: +USB1_P -USB1_N
differential pair USB1_L: +USB1_L_P -USB1_L_N
differential pair USB1_CON: +USB1_CON_P -USB1_CON_N
differential pair USB0_L: +USB0_L_P -USB0_L_N
differential pair USB0_CON: +USB0_CON_P -USB0_CON_N
differential pair HDMI_OUT_D2: +HDMI_OUT_D2_P -HDMI_OUT_D2_N
differential pair HDMI_OUT_D1: +HDMI_OUT_D1_P -HDMI_OUT_D1_N
differential pair HDMI_OUT_D0: +HDMI_OUT_D0_P -HDMI_OUT_D0_N
differential pair HDMI_OUT_CLK: +HDMI_OUT_CLK_P -HDMI_OUT_CLK_N
differential pair HDMI_IN_D2: +HDMI_IN_D2_P -HDMI_IN_D2_N
differential pair HDMI_IN_D1: +HDMI_IN_D1_P -HDMI_IN_D1_N
differential pair HDMI_IN_D0: +HDMI_IN_D0_P -HDMI_IN_D0_N
differential pair HDMI_IN_CLK: +HDMI_IN_CLK_P -HDMI_IN_CLK_N
differential pair CSI_D1: +CSI_D1_P -CSI_D1_N
differential pair CSI_D0: +CSI_D0_P -CSI_D0_N
differential pair CSI_CLK0: +CSI_CLK0_P -CSI_CLK0_N
differential pair MX3: +MX0_P -MX0_N
differential pair MX2: +MX2_P -MX2_N
differential pair MX1: +MX1_P -MX1_N
differential pair MX0: +MX3_P -MX3_N
differential pair SATA_RX: +SATA_RX_P -SATA_RX_N
differential pair SATA_TX: +SATA_TX_P -SATA_TX_N
differential pair TRD0: +TRD0_P -TRD0_N
differential pair TRD1: +TRD1_P -TRD1_N
differential pair TRD2: +TRD2_P -TRD2_N
differential pair TRD3: +TRD3_P -TRD3_N
differential pair USB0: +USB0_P -USB0_N
differential pair USB_OTG_CON: +USB_OTG_CON_P -USB_OTG_CON_N
differential pair USB_OTG: +USB_OTG_P -USB_OTG_N

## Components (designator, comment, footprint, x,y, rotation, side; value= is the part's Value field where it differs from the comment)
C1 "22u" C0603 1700.79,1255.91 r90 bottom
C2 "22u" C0603 1795.28,1145.67 r0 bottom
C3 "22u" C0603 1586.61,1149.61 r180 bottom
C4 "100n" C0402 1755.91,1240.16 r90 bottom
C5 "100n" C0402 1779.53,1094.49 r0 bottom
C6 "100n" C0402 1692.91,1094.49 r180 bottom
C7 "100n" C0402 1645.67,1240.16 r90 bottom
C8 "100n" C0402 216.54,645.67 r180 bottom
C9 "100n" C0402 1956.69,2692.91 r180 top
C10 "10u" C0603 2570.87,141.73 r270 bottom
C11 "47u" C0805 2047.24,358.27 r270 top
C12 "100n" C0402 1602.36,1240.16 r90 bottom
C13 "100n" C0402 1444.88,1240.16 r90 bottom
C14 "100n" C0402 1232.28,2196.85 r270 bottom
C15 "100n" C0402 1169.29,1228.35 r90 bottom
C16 "22u" C0603 1248.03,1248.03 r0 bottom
C17 "47u" C0805 1814.96,811.02 r180 top
C18 "1u" C0402 503.94,2027.56 r0 top
C19 "4u7" C0402 413.39,2059.06 r90 top
C20 "10u" C0603 515.75,1838.58 r90 top
C21 "2700pF" C0402 318.9,1854.33 r90 top
C22 "100n" C0402 2460.63,1468.5 r0 top
C23 "100n" C0402 2362.2,1468.5 r0 top
C24 "100n" C0402 2566.93,1468.5 r0 top
C25 "100n" C0402 2637.8,1488.19 r90 top
C26 "100n" C0402 271.65,2244.09 r90 top
C27 "100n" C0402 2035.43,3181.1 r180 bottom
C28 "100n" C0402 830.71,3181.1 r0 bottom
C29 "22u" C0603 1917.32,826.77 r270 top
C30 "22u" C0603 1917.32,818.9 r270 bottom
C31 "10u" C0603 287.4,1000 r270 top
C32 "100n" C0402 299.21,1078.74 r0 top
C33 "100n" C0402 1952.76,956.69 r180 top
C34 "100n" C0402 1736.22,2787.4 r0 bottom
C35 "100n" C0402 2389.76,1125.98 r180 bottom
C36 "100n" C0402 673.23,3062.99 r0 bottom
C37 "22u" C0603 1614.17,421.26 r180 top
C38 "22u" C0603 1645.67,511.81 r90 top
C39 "2u2" C0402 1700.79,496.06 r90 top
C40 "2u2" C0402 1925.2,503.94 r90 top
C41 "100n" C0402 1492.13,653.54 r180 bottom
C42 "100n" C0402 1342.52,625.98 r0 bottom
C43 "100n" C0402 1342.52,578.74 r0 bottom
C44 "100n" C0402 1417.32,673.23 r270 bottom
C45 "220pF" C0402 1429.13,606.3 r180 bottom
C46 "220pF" C0402 1429.13,559.06 r0 bottom
C47 "220pF" C0402 1429.13,496.06 r180 bottom
C48 "15pF" C0402 1244.09,755.91 r180 top
C49 "15pF" C0402 1417.32,755.91 r0 top
C50 "220pF" C0402 1342.52,523.62 r180 bottom
C51 "220pF" C0402 1342.52,673.23 r0 bottom
C52 "100n" C0402 1429.13,448.82 r0 bottom
C53 "100n" C0402 1342.52,484.25 r0 bottom
C54 "100n" C0402 1342.52,444.88 r0 bottom
C55 "100n" C0402 1255.91,468.5 r180 bottom
C56 "1u" C0402 874.02,322.83 r90 top
C57 "4u7" C0402 874.02,212.6 r270 top
C58 "10u" C0603 1078.74,366.14 r180 top
C59 "2700pF" C0402 1149.61,224.41 r0 top
C60 "10u" C0603 389.76,1673.23 r0 top
C61 "22u" C0603 1984.25,488.19 r90 top
C62 "22u" C0603 2039.37,366.14 r270 bottom
C63 "22u" C0603 2051.18,488.19 r90 top
C64 "100n" C0402 1929.13,330.71 r270 top
C65 "22u" C0603 2255.91,889.76 r90 top
C66 "22u" C0603 2318.9,889.76 r90 top
C67 "2u2" C0402 2200.79,885.83 r90 top
C68 "2u2" C0402 1972.44,830.71 r270 top
C69 "100n" C0402 350.39,1618.11 r180 top
C70 "22u" C0603 1822.83,889.76 r180 top
C71 "100n" C0402 937.01,393.7 r0 top
C72 "100n" C0402 846.46,393.7 r0 top
C73 "100n" C0402 665.35,389.76 r0 top
C74 "100n" C0402 299.21,814.96 r90 top
C75 "100n" C0402 976.38,1551.18 r90 bottom
C76 "100n" C0402 2000,1681.1 r90 bottom
C77 "100n" C0402 677.17,212.6 r90 top
C78 "10uF / 16V" C0805 775.59,212.6 r0 top
C79 "100n" C0402 2578.74,240.16 r90 bottom
C89 "1u" C0402 1334.65,2582.68 r270 top
C90 "4u7" C0402 1334.65,2677.17 r90 top
C91 "10u" C0603 1212.6,2519.69 r0 top
C92 "2700pF" C0402 1098.43,2700.79 r180 top
C106 "22u" C0805 385.83,2244.09 r0 top
C108 "100n" C0402 2661.42,988.19 r270 top
C114 "100n" C0402 1818.9,1866.14 r0 bottom
C115 "100n" C0402 2755.91,2188.98 r0 bottom
C116 "100n" C0402 1838.58,1984.25 r90 bottom
C117 "100n" C0402 1838.58,2165.35 r270 bottom
C118 "100n" C0402 1838.58,2283.46 r90 bottom
C119 "1000pF, 2kV" C1206 2696.85,2019.69 r270 bottom
C156 "330u" C2917 2594.49,2456.69 r0 top locked
C158 "100n" C0402 338.58,2035.43 r180 top
C159 "330u" C2917 2622.05,3326.77 r180 top locked
C160 "100n" C0402 2409.45,2818.9 r180 bottom
C161 "100n" C0402 2751.97,2803.15 r180 bottom
C165 "100n" C0402 2334.65,2779.53 r180 top
C171 "100n" C0402 622.05,2539.37 r90 top
C176 "100n" C0402 736.22,2720.47 r180 top
C177 "100n" C0402 1255.91,523.62 r180 bottom
C183 "220pF" C0402 1255.91,614.17 r0 bottom
C184 "220pF" C0402 1255.91,661.42 r0 bottom
C185 "10u" C0603 1212.6,413.39 r0 bottom
C187 "100n" C0402 1255.91,566.93 r180 bottom
C188 "100n" C0402 1188.98,633.86 r270 bottom
C190 "100n" C0402 1295.28,720.47 r180 bottom
C198 "100n" C0402 307.09,3133.86 r90 bottom
C200 "100n" C0402 307.09,2783.46 r90 bottom
C203 "100n" C0402 1870.08,2681.1 r270 top
C230 "100n" C0402 590.55,2374.02 r270 top
C231 "22u" C0603 1523.62,1251.97 r0 bottom
C232 "22u" C0603 1287.4,2181.1 r270 bottom
C257 "330u" C2917 511.81,1456.69 r270 top locked
C258 "330u" C2917 511.81,1082.68 r270 top locked
C259 "100n" C0402 775.59,807.09 r0 bottom
C260 "100n" C0402 649.61,1330.71 r90 top
C261 "100n" C0402 641.73,1582.68 r90 top
C262 "4u7" C0402 696.85,1330.71 r90 top
C263 "4u7" C0402 377.95,1393.7 r270 top
C264 "4u7" C0402 799.21,720.47 r270 bottom
C265 "100n" C0402 751.97,720.47 r270 bottom
C266 "100n" C0402 645.67,1137.8 r270 top
C267 "100n" C0402 582.68,1673.23 r180 top
C268 "100n" C0402 377.95,1480.31 r90 top
C381 "22u" C0603 2318.9,704.72 r90 top
CR1 "Mini PCIe Card" "MINI_PCIE_FULL CARD" 511.81,1771.65 r0 bottom locked
CR2 "Micro SD Card" Micro_SD_card 568.9,1996.06 r270 top
D1 "SS10P4-M3/86A" "TO-277A (SMPC)" 2456.69,492.13 r0 top
D2 "BAT54HT1G" SOD323 322.83,889.76 r180 top
D3 "BAT54HT1G" SOD323 2500,956.69 r90 top
D4 "PGB1010603MR" C0603 610.24,196.85 r180 bottom
D5 "Red" LED_0603 118.11,354.33 r180 top
D6 "BAT54HT1G" SOD323 850.39,858.27 r270 bottom
D7 "BAT54HT1G" SOD323 838.58,925.2 r0 top
D8 "PGB1010603MR" C0603 492.13,196.85 r0 bottom
D9 "BGX50AE6327" SOT143 318.9,2137.8 r270 top
D10 "BGX50AE6327" SOT143 2409.45,2909.45 r90 bottom
D11 "BGX50AE6327" SOT143 2779.53,2893.7 r90 bottom
D12 "PGB1010603MR" C0603 401.57,224.41 r90 bottom
D13 "PGB1010603MR" C0603 787.4,196.85 r0 bottom
D14 "Green" LED_0603 118.11,480.31 r180 top
D15 "MBR140SFT1G" SOD-123FL 529.53,210.63 r180 top
D16 "BAT54HT1G" SOD323 181.1,1031.5 r270 bottom
D17 "Red" LED_0603 2913.39,2484.25 r270 top
D18 "Red" LED_0603 3070.87,2484.25 r270 top
D19 "PGB1010603MR" C0603 263.78,1992.13 r270 top
D27 "RB751V-40-TP" SOD323 673.23,2460.63 r180 top
FB1 "MPZ1608S601A 600OHM/1A" C0603 2389.76,2716.54 r0 top
FB2 "MPZ1608S601A 600OHM/1A" C0603 2740.16,3307.09 r90 bottom
FB3 "BLM15AX601SN1D" C0402 1492.13,704.72 r180 bottom
FB4 "BLM15AX601SN1D" C0402 1342.52,397.64 r180 bottom
FB5 "BLM15AX601SN1D" C0402 1188.98,488.19 r270 bottom
FB6 "220R, 2.5A" C0603 397.64,2456.69 r180 top
FB7 "220R, 2.5A" C0603 370.08,1732.28 r180 top
FB8 "BLM15AX601SN1D" C0402 1169.29,566.93 r180 bottom
FB9 "220R, 2.5A" C0603 696.85,1196.85 r90 top
FB10 "220R, 2.5A" C0603 511.81,1732.28 r180 top
FB11 "BLM15AX601SN1D" C0402 1228.35,744.09 r90 bottom
FB12 "220R, 2.5A" C0603 338.58,2456.69 r0 top
FB24 "MPZ1608S601A 600OHM/1A" C0603 500,2240.16 r90 top
FID1 "FID_1MMC" FID_40X120D 3066.93,393.7 r0 top
FID2 "FID_1MMC" FID_40X120D 259.84,464.57 r90 top
FID3 "FID_1MMC" FID_40X120D 397.64,3452.76 r90 top
FID4 "FID_1MMC" FID_40X120D 3031.5,3149.61 r90 top
FID5 "FID_1MMC" FID_40X120D 3066.93,393.7 r90 bottom
FID6 "FID_1MMC" FID_40X120D 259.84,464.57 r90 bottom
FID7 "FID_1MMC" FID_40X120D 397.64,3452.76 r90 bottom
FID8 "FID_1MMC" FID_40X120D 3031.5,3149.61 r90 bottom
J1 "DF40C-100DS-0.4V(51)" DF40C-100DS-0.4V(51)_V1.1 1397.64,1098.43 r270 top locked
J2 "DF40C-100DS-0.4V(51)" DF40C-100DS-0.4V(51)_V1.1 862.2,1633.86 r0 top locked
J3 "DF40C-100DS-0.4V(51)" DF40C-100DS-0.4V(51)_V1.1 1287.4,2212.6 r270 top locked
J4 "5787617-1" USB-2A 2641.73,2893.7 r270 top locked
J5 "2-406549-1" RJ45LED 2854.33,2007.87 r0 top locked
J6 "47151-0001" "HDMI V1.1" 2893.7,1181.1 r0 top locked
J7 "PJ-002AH" POWER_JACK_5.5_2.1MM_NS_V1.1 2696.85,511.81 r270 top locked
J8 "0022112022" HDR_1X2_2.54MM_MOLEX_KK 2657.48,177.17 r0 top
J9 "0471554001" SATA_VERTICAL 1929.13,125.98 r0 top
J10 "HDR 1x6, 2.54mm" Hdr_1x6_2.54mm 905.51,118.11 r270 top locked
J11 "0467651001" MICRO_HDMI 0,708.66 r270 top locked
J12 "1-84952-5" ZIF_RA_BOTTOM_15X1MM 196.85,1417.32 r270 top locked
J13 "MM60-52B1-E1-R650" MINI_PCIE_52PIN_CARD_CON 511.81,688.98 r0 bottom locked
J14 "USB MICRO AB" USB_MICRO_AB 86.61,2161.42 r0 top locked
J15 "693071010811" 693071010811 401.57,2169.29 r270 bottom locked
J16 "HDR 2x7, BOXED" HDR_2x7_2.54MM_BOXED 551.18,2874.02 r90 top locked
J17 "HDR 2x7, BOXED" HDR_2x7_2.54MM_BOXED 551.18,3267.72 r90 top locked
J18 "HDR 2x5, BOXED" HDR_2x5_2.54mm_BOXED 1614.17,2874.02 r90 top locked
J19 "HDR 2x7, BOXED" HDR_2x7_2.54MM_BOXED 1614.17,3267.72 r90 top locked
J20 "MM60-EZH059-B5-R650" MINI_PCIE_52PIN_CARD_LATCH 2464.57,574.8 r0 bottom locked
JP1 "HDR 1x2" HDR_1x2_2.54MM 1208.66,118.11 r270 top
L1 "1u5" IHLP_204MILX216MIL 1807.09,657.48 r0 top
L2 "1u5" IHLP_204MILX216MIL 2129.92,657.48 r180 top
L3 "ACM2012-900-2P-T002" ACM2012 2259.84,2901.57 r180 bottom
L4 "ACM2012-900-2P-T002" ACM2012 488.19,2145.67 r180 top
L5 "ACM2012-900-2P-T002" ACM2012 2901.57,2763.78 r270 bottom
L6 "ACM2012-900-2P-T002" ACM2012 688.98,1409.45 r0 top
M1 "iMX6 TinyRex Module V1I1 3D" "iMX6 TinyRex Module 3D" 748.03,984.25 r0 top
MH1 "MH_7.4MMC_3.2MMD" MH_7.4MMD_3.2MMD 157.48,157.48 r0 top
MH2 "MH_7.4MMC_3.2MMD" MH_7.4MMD_3.2MMD 2992.13,157.48 r0 top
MH3 "MH_7.4MMC_3.2MMD" MH_7.4MMD_3.2MMD 2992.13,3385.83 r0 top locked
MH4 "MH_7.4MMC_3.2MMD" MH_7.4MMD_3.2MMD 157.48,3385.83 r0 top
MH5 "MH_5MMC_2MMD" MH_5MMD_2MMD 834.65,1070.87 r0 top locked
MH6 "MH_5MMC_2MMD" MH_5MMD_2MMD 1700.79,2393.7 r0 top locked
MH9 "MH_5.2MMC_2.7MMD" MH_5.2MMD_2.7MMD 472.44,433.07 r0 top locked
MH10 "MH_5.2MMC_2.7MMD" MH_5.2MMD_2.7MMD 2204.72,433.07 r0 top locked
MH11 "MH_5.2MMC_2.7MMD" MH_5.2MMD_2.7MMD 2204.72,2598.43 r0 top
MH12 "MH_5.2MMC_2.7MMD" MH_5.2MMD_2.7MMD 472.44,2598.43 r0 top locked
NUT3 "M2" "NUT A4 SS M2" 834.69,1070.87 r0 top
NUT4 "M2" "NUT A4 SS M2" 1700.81,2393.71 r0 top
Q1 "DMP2035U-7" SOT-23-3-123 283.46,2362.2 r90 top
Q2 "DMP2035U-7" SOT-23-3-123 444.88,2362.2 r270 top
Q3 "2N7002BKW,115" SC70_SOT323 645.67,2216.54 r270 top
Q4 "2N7002BKW,115" SC70_SOT323 125.98,385.83 r180 bottom
Q5 "2N7002BKW,115" SC70_SOT323 370.08,263.78 r90 top
Q6 "2N7002BKS,115" SOT363 578.74,287.4 r90 bottom
Q7 "SI4425BDY-T1-E3" 8_SOIC_3.9MM 2456.69,177.17 r90 top
Q8 "2N7002BKS,115" SOT363 763.78,303.15 r90 bottom
Q9 "2N7002BKW,115" SC70_SOT323 3035.43,2728.35 r270 bottom
Q10 "MMBT3906,215" SOT-23-3-123 2472.44,149.61 r0 bottom
Q11 "2N7002BKW,115" SC70_SOT323 3035.43,2602.36 r90 bottom
R1 "10k" R0402 1657.48,940.94 r270 bottom
R2 "10k" R0402 1712.6,940.94 r270 bottom
R3 "10k" R0402 1657.48,724.41 r90 bottom
R4 "10k" R0402 1712.6,724.41 r90 bottom
R5 "0R" R0402 314.96,358.27 r180 bottom
R6 "4k99" R0402 1129.92,874.02 r270 top
R7 "4k99" R0402 1129.92,787.4 r90 top
R8 "0R" R0402 996.06,826.77 r0 top
R9 "0R" R0402 968.5,893.7 r0 top
R10 "10k" R0402 988.19,1346.46 r90 bottom
R11 "10k" R0402 763.78,389.76 r180 top
R12 "47k" R0402 976.38,948.82 r180 top
R13 "47k" R0402 1051.18,893.7 r0 top
R14 "0R" R0402 2783.46,1098.43 r270 bottom
R15 "0R" R0402 2720.47,1098.43 r90 bottom
R16 "0R" R0402 2720.47,1011.81 r270 bottom
R17 "4k99" R0402 2653.54,1011.81 r90 bottom
R18 "2k1" R0402 437.01,1787.4 r0 top
R19 "4k99" R0402 2653.54,1098.43 r270 bottom
R20 "2k4" R0402 350.39,1787.4 r0 top
R21 "27k" R0402 2555.12,988.19 r90 top
R22 "0R" R0402 988.19,1267.72 r270 bottom
R23 "10k" R0402 1956.69,2641.73 r0 top
R24 "10k" R0402 1645.67,330.71 r270 top
R25 "100k" R0402 1696.85,330.71 r90 top
R26 "10k" R0402 2460.63,1519.69 r0 top
R27 "10k" R0402 1590.55,330.71 r270 top
R28 "10k" R0402 2393.7,877.95 r0 top
R29 "100k" R0402 2393.7,940.94 r180 top
R30 "0R" R0402 1409.45,2511.81 r0 top
R31 "0R" R0402 1413.39,2677.17 r90 top
R32 "10k" R0402 2401.57,3035.43 r270 bottom
R33 "10k" R0402 3055.12,2476.38 r270 bottom
R34 "0R" R0402 1220.47,2015.75 r0 bottom
R35 "22R" R0402 1307.09,2015.75 r0 bottom
R36 "47k" R0402 2429.13,1003.94 r0 top
R37 "10k" R0402 362.2,968.5 r180 top
R38 "100k" R0402 192.91,929.13 r0 bottom
R39 "0R" R0402 251.97,688.98 r0 bottom
R40 "47k" R0402 236.22,751.97 r90 bottom
R41 "0R" R0402 2342.52,1003.94 r180 top
R42 "22R" R0402 1346.46,2015.75 r180 bottom
R43 "22R" R0402 1385.83,2015.75 r0 bottom
R44 "10k" R0402 1137.8,1551.18 r270 bottom
R45 "10k" R0402 574.8,2464.57 r90 top
R46 "0R" R0402 2362.2,1519.69 r180 top
R47 "15k" R0402 2610.24,988.19 r90 top
R48 "47k" R0402 661.42,862.2 r90 top
R49 "47k" R0402 728.35,862.2 r90 top
R50 "27k" R0402 822.83,866.14 r180 top
R51 "1k" R0402 255.91,984.25 r180 bottom
R52 "10k" R0402 2456.69,3035.43 r90 bottom
R53 "10k" R0402 2984.25,2460.63 r0 bottom
R54 "3k3" R0402 838.58,299.21 r90 bottom
R55 "3k3" R0402 578.74,287.4 r270 top
R56 "3k3" R0402 653.54,307.09 r270 bottom
R57 "3k3" R0402 681.1,303.15 r270 top
R58 "0R" R0402 775.59,303.15 r90 top
R59 "0R" R0402 527.56,287.4 r270 top
R60 "0R" R0402 629.92,287.4 r90 top
R61 "0R" R0402 732.28,303.15 r270 top
R62 "0R" R0402 1850.39,1681.1 r90 bottom
R63 "0R" R0402 503.94,2460.63 r0 top
R64 "10k" R0402 570.87,2480.31 r0 bottom
R65 "10k" R0402 748.03,1559.06 r270 bottom
R66 "33R" R0402 1224.41,374.02 r90 top
R67 "1k" R0402 787.4,2464.57 r270 bottom
R68 "240R" R0402 2917.32,2500 r90 bottom
R69 "240R" R0402 2984.25,2515.75 r180 bottom
R70 "3k3" R0402 625.98,381.89 r0 bottom
R71 "3k3" R0402 759.84,393.7 r0 bottom
R72 "390k" R0402 1330.71,755.91 r0 top
R81 "10k" R0402 314.96,303.15 r0 bottom
R82 "3k" R0402 1165.35,354.33 r90 top
R83 "2k4" R0402 1149.61,279.53 r180 top
R84 "75R" R0402 2590.55,1854.33 r0 bottom
R85 "75R" R0402 2590.55,2003.94 r0 bottom
R86 "75R" R0402 2590.55,2153.54 r0 bottom
R87 "75R" R0402 2590.55,2303.15 r0 bottom
R100 "1k, 1206, 0.5W" R1206 2803.15,314.96 r90 bottom
R104 "0R" R0402 885.83,744.09 r0 bottom
R105 "0R" R0402 1062.99,948.82 r0 top
R109 "0R" R0402 1492.13,791.34 r270 top
R117 "10k" R0402 559.06,2724.41 r0 top
R135 "0R" R0402 775.59,574.8 r180 bottom
R136 "0R" R0402 775.59,633.86 r0 bottom
R138 "0R" R0402 362.2,1027.56 r180 top
R139 "0R" R0402 952.76,1751.97 r0 bottom
R140 "10k" R0402 322.83,2976.38 r0 bottom
R141 "33R" R0402 307.09,3047.24 r270 bottom
R144 "240R" R0402 62.99,448.82 r270 bottom
R145 "240R" R0402 118.11,484.25 r270 bottom
R146 "240R" R0402 232.28,358.27 r90 top
R147 "10k" R0402 307.09,2610.24 r270 bottom
R148 "240R" R0402 287.4,358.27 r90 top
R149 "33R" R0402 307.09,2696.85 r270 bottom
R153 "0R" R0402 625.98,2708.66 r270 top
R155 "0R" R0402 657.48,2480.31 r180 bottom
R162 "0R" R0402 185.04,720.47 r270 bottom
R163 "0R" R0402 578.74,842.52 r0 top
R164 "0R" R0402 665.35,940.94 r0 top
R165 "0R" R0402 1066.93,818.9 r270 top
R166 "22R" R0402 1590.55,807.09 r0 top
R167 "22R" R0402 1590.55,858.27 r0 top
R168 "22R" R0402 1590.55,755.91 r0 top
R169 "22R" R0402 1590.55,704.72 r0 top
R174 "0R" R0402 366.14,830.71 r0 top
R201 "10k" R0402 673.23,2311.02 r0 top
R204 "10k" R0402 1893.7,2570.87 r90 top
R206 "10k" R0402 1535.43,2708.66 r90 top
R211 "1M02" R0402 1960.63,401.57 r0 top
R213 "113k" R0402 1980.32,330.71 r90 top
R214 "100k" R0402 539.37,2374.02 r270 top
R216 "1M02" R0402 1929.13,905.51 r180 top
R217 "182k" R0402 1866.14,952.76 r0 top
R220 "0R" R0402 1413.39,2582.68 r270 top
R224 "10k" R0402 1322.83,2511.81 r180 top
R225 "5k1" R0402 1110.24,2515.75 r0 top
R226 "2k4" R0402 1082.68,2633.86 r270 top
R247 "10k" R0402 803.15,1559.06 r270 bottom
R292 "11k8" R0402 2712.6,377.95 r0 bottom
R293 "10k" R0402 2574.8,307.09 r180 bottom
R296 "10k5" R0402 2625.98,377.95 r0 bottom
R301 "470k" R0402 2527.56,240.16 r270 bottom
R304 "0R" R0402 728.35,2464.57 r90 bottom
SCR3 "M2x8mm" "SCREW M2x8" 834.66,1070.86 r0 top
SCR4 "M2x8mm" "SCREW M2x8" 1700.85,2393.7 r0 top
SPA3 "2.5/4.5x1.5mm" "SPACER 2.5/4.5X1.5MM" 835,1071.06 r0 top
SPA4 "2.5/4.5x1.5mm" "SPACER 2.5/4.5X1.5MM" 1701.14,2393.9 r0 top
SW1 "FSMRA2JH" FSMRA2JH 165.35,3031.5 r270 top
SW2 "FSMRA3JH" FSMRA3JH 165.35,2637.8 r270 top
T1 "H5007NL" H5007NL 2204.72,2129.92 r0 bottom locked
TP1 "TP_25MILC" TP_25C 468.5,1830.71 r90 bottom
TP2 "TP_25MILC" TP_25C 1614.17,877.95 r90 bottom
TP3 "TP_25MILC" TP_25C 1712.6,877.95 r90 bottom
TP4 "TP_25MILC" TP_25C 1118.11,385.83 r90 bottom
TP5 "TP_25MILC" TP_25C 1614.17,787.4 r270 bottom
TP6 "TP_25MILC" TP_25C 1712.6,787.4 r270 bottom
TP7 "TP_25MILC" TP_25C 1566.93,2208.66 r90 bottom
TP8 "TP_25MILC" TP_25C 1173.23,984.25 r90 bottom
TP9 "TP_25MILC" TP_25C 2271.65,574.8 r90 bottom
TP10 "TP_25MILC" TP_25C 1200.79,874.02 r90 bottom
TP11 "TP_25MILC" TP_25C 748.03,2106.3 r0 bottom
TP12 "TP_25MILC" TP_25C 2062.99,456.69 r90 bottom
TP13 "TP_25MILC" TP_25C 1921.26,913.39 r90 bottom
TP14 "TP_25MILC" TP_25C 787.4,2047.24 r0 bottom
TP15 "TP_25MILC" TP_25C 1338.58,2224.41 r90 bottom
U1 "ADV7610BBCZ-P" 76_CSP_BGA 1338.58,551.18 r0 top locked
U2 "TPS74801DRCR" "DRC (S-PVSON-N10)" 984.25,267.72 r0 top locked
U3 "SN74LVC1G17DCKR" SC70_5 2385.83,1043.31 r90 bottom
U4 "TPD12S520DBTR" TSSOP_38 779.53,618.11 r180 top locked
U5 "CM2020-00TR" TSSOP_38 2515.75,1240.16 r0 top
U6 "TPS74801DRCR" "DRC (S-PVSON-N10)" 413.39,1921.26 r270 top locked
U7 "MIC2026-1YM TR" 8_SOIC_3.9MM 2338.58,2948.82 r270 top locked
U8 "SST25VF016B-75-4I-QAF-ND" WSON8_6X5MM 1704.72,2625.98 r0 top
U9 "TPS63020DSJR" "DSJ (R-PVSON-N14)" 1814.96,448.82 r180 top locked
U10 "TPS63020DSJR" "DSJ (R-PVSON-N14)" 2090.55,881.89 r0 top locked
U11 "TPS74801DRCR" "DRC (S-PVSON-N10)" 1224.41,2637.8 r180 top locked
U12 "TS3USB221ERSER" "RSE (R-PUQFN-N10)" 1960.63,2688.98 r270 bottom
U13 "TS3USB221ERSER" "RSE (R-PUQFN-N10)" 1051.18,1553.67 r270 bottom
U14 "SN74LVC1G08DCKR" SC70_5 1925.2,1657.48 r90 bottom
U16 "M74VHC1GT126DF1G" SC70_5 673.23,2381.89 r180 top
U20 "SN74LVC1G08DCKR" SC70_5 712.6,2539.37 r180 top
U21 "SN74LVC1G08DCKR" SC70_5 712.6,2637.8 r0 top
U27 "TL431AQDBZR" SOT-23-3-123 2688.98,287.4 r270 bottom
Y1 "28.63636MHz" ABM3B 1330.71,866.14 r0 top

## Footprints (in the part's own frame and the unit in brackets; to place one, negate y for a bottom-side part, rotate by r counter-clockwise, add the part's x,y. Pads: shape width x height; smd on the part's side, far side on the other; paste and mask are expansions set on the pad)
8_SOIC_3.9MM [mm]
  rect 1.2x0.58 smd: 1(-2.8,1.905) 2(-2.8,0.635) 3(-2.8,-0.635) 4(-2.8,-1.905) 5(2.8,-1.905) 6(2.8,-0.635) 7(2.8,0.635) 8(2.8,1.905)
  silkscreen extent -1.91,-2.54 1.91,2.54, body extent -3,-2.45 3,2.45, height 1.75
76_CSP_BGA [mm] "Creator MM"
  round 0.25 smd mask+0.05: A1(-2.25,2.25) A2(-1.75,2.25) A3(-1.25,2.25) A4(-0.75,2.25) A5(-0.25,2.25) A6(0.25,2.25) A7(0.75,2.25) A8(1.25,2.25) A9(1.75,2.25) A10(2.25,2.25) B1(-2.25,1.75) B2(-1.75,1.75) B3(-1.25,1.75) B4(-0.75,1.75) B5(-0.25,1.75) B6(0.25,1.75) B7(0.75,1.75) B8(1.25,1.75) B9(1.75,1.75) B10(2.25,1.75) C1(-2.25,1.25) C2(-1.75,1.25) C9(1.75,1.25) C10(2.25,1.25) D1(-2.25,0.75) D2(-1.75,0.75) D4(-0.75,0.75) D5(-0.25,0.75) D6(0.25,0.75) D7(0.75,0.75) D9(1.75,0.75) D10(2.25,0.75) E1(-2.25,0.25) E2(-1.75,0.25) E4(-0.75,0.25) E7(0.75,0.25) E9(1.75,0.25) E10(2.25,0.25) F1(-2.25,-0.25) F2(-1.75,-0.25) F4(-0.75,-0.25) F7(0.75,-0.25) F9(1.75,-0.25) F10(2.25,-0.25) G1(-2.25,-0.75) G2(-1.75,-0.75) G4(-0.75,-0.75) G5(-0.25,-0.75) G6(0.25,-0.75) G7(0.75,-0.75) G9(1.75,-0.75) G10(2.25,-0.75) H1(-2.25,-1.25) H2(-1.75,-1.25) H9(1.75,-1.25) H10(2.25,-1.25) J1(-2.25,-1.75) J2(-1.75,-1.75) J3(-1.25,-1.75) J4(-0.75,-1.75) J5(-0.25,-1.75) J6(0.25,-1.75) J7(0.75,-1.75) J8(1.25,-1.75) J9(1.75,-1.75) J10(2.25,-1.75) K1(-2.25,-2.25) K2(-1.75,-2.25) K3(-1.25,-2.25) K4(-0.75,-2.25) K5(-0.25,-2.25) K6(0.25,-2.25) K7(0.75,-2.25) K8(1.25,-2.25) K9(1.75,-2.25) K10(2.25,-2.25)
  silkscreen extent -3.1,-3.1 3.1,3.1, body extent -3.1,-3.1 3.1,3.1, height 0.8
693071010811 [mm]
  rect 0.8x1.5 smd mask+0.09: 1(-1.815,3.225) 2(-0.715,2.825) 3(0.385,3.225) 4(1.485,3.425) 5(2.585,3.225) 6(3.685,3.425) 7(4.785,3.225) 8(5.885,3.225)
  rect 1.8x1.4 smd: 9(-0.625,-7.075) 10(5.075,-7.075)
  rect 1.5x1.9 smd: 11(6.775,6.075)
  rect 1.6x1.9 smd: 12(-6.675,7.075)
  silkscreen extent -7.07,-7.57 7.22,9.6, body extent -6.87,-7.46 7.13,7.75, height 1.83
ABM3B [mm] "Creator MM"
  rect 1.8x1.2 smd: 1(-2,-1.2) 2(2,-1.2) 3(2,1.2) 4(-2,1.2)
  silkscreen extent -3.4,-1.8 2.6,1.7, body extent -2.5,-1.6 2.5,1.6, height 1.12
ACM2012 [mm]
  rect 0.75x0.4 smd mask+0.076: 1(-0.925,0.4) 2(-0.925,-0.4) 3(0.925,-0.4) 4(0.925,0.4)
  silkscreen extent -1.1,-0.9 1.1,0.9, body extent -1.2,-0.7 1.2,0.7, height 1.3
C0402 [mm]
  rect 0.5x0.5 smd: 1(-0.5,0) 2(0.5,0)
  silkscreen extent -1,-0.5 1,0.5, body extent -0.5,-0.25 0.5,0.25, height 0.56
C0603 [mm]
  rect 0.8x0.8 smd: 1(-0.75,0) 2(0.75,0)
  silkscreen extent -1.4,-0.7 1.4,0.7, body extent -0.8,-0.42 0.8,0.44, height 0.95
C0805 [mm]
  rect 0.9x1.3 smd: 1(-0.95,0) 2(0.95,0)
  silkscreen extent -1.78,-1.02 1.78,1.02, body extent -1,-0.6 1,0.6, height 1.5
C1206 [mm]
  rect 0.9x1.6 smd: 1(-1.55,0) 2(1.55,0)
  silkscreen extent -2.29,-1.14 2.29,1.14, body extent -1.6,-0.8 1.6,0.8, height 1.8
C2917 [mm] "Creator MM. Footprint density lvl B"
  rect 2.37x2.43 smd: 1(-3.12,0) 2(3.12,0)
  silkscreen extent -4.64,-2.65 4.65,2.65, body extent -3.79,-2.3 3.81,2.3, height 3.1
DF40C-100DS-0.4V(51)_V1.1 [mm] "Creator MM. Update: Replaced part of silkcreen by copper"
  rect 0.7x0.2 smd mask+0.03: 1(1.54,9.8) 2(-1.54,9.8) 3(1.54,9.4) 4(-1.54,9.4) 5(1.54,9) 6(-1.54,9) 7(1.54,8.6) 8(-1.54,8.6) 9(1.54,8.2) 10(-1.54,8.2) 11(1.54,7.8) 12(-1.54,7.8) 13(1.54,7.4) 14(-1.54,7.4) 15(1.54,7) 16(-1.54,7) 17(1.54,6.6) 18(-1.54,6.6) 19(1.54,6.2) 20(-1.54,6.2) 21(1.54,5.8) 22(-1.54,5.8) 23(1.54,5.4) 24(-1.54,5.4) 25(1.54,5) 26(-1.54,5) 27(1.54,4.6) 28(-1.54,4.6) 29(1.54,4.2) 30(-1.54,4.2) 31(1.54,3.8) 32(-1.54,3.8) 33(1.54,3.4) 34(-1.54,3.4) 35(1.54,3) 36(-1.54,3) 37(1.54,2.6) 38(-1.54,2.6) 39(1.54,2.2) 40(-1.54,2.2) 41(1.54,1.8) 42(-1.54,1.8) 43(1.54,1.4) 44(-1.54,1.4) 45(1.54,1) 46(-1.54,1) 47(1.54,0.6) 48(-1.54,0.6) 49(1.54,0.2) 50(-1.54,0.2) 51(1.54,-0.2) 52(-1.54,-0.2) 53(1.54,-0.6) 54(-1.54,-0.6) 55(1.54,-1) 56(-1.54,-1) 57(1.54,-1.4) 58(-1.54,-1.4) 59(1.54,-1.8) 60(-1.54,-1.8) 61(1.54,-2.2) 62(-1.54,-2.2) 63(1.54,-2.6) 64(-1.54,-2.6) 65(1.54,-3) 66(-1.54,-3) 67(1.54,-3.4) 68(-1.54,-3.4) 69(1.54,-3.8) 70(-1.54,-3.8) 71(1.54,-4.2) 72(-1.54,-4.2) 73(1.54,-4.6) 74(-1.54,-4.6) 75(1.54,-5) 76(-1.54,-5) 77(1.54,-5.4) 78(-1.54,-5.4) 79(1.54,-5.8) 80(-1.54,-5.8) 81(1.54,-6.2) 82(-1.54,-6.2) 83(1.54,-6.6) 84(-1.54,-6.6) 85(1.54,-7) 86(-1.54,-7) 87(1.54,-7.4) 88(-1.54,-7.4) 89(1.54,-7.8) 90(-1.54,-7.8) 91(1.54,-8.2) 92(-1.54,-8.2) 93(1.54,-8.6) 94(-1.54,-8.6) 95(1.54,-9) 96(-1.54,-9) 97(1.54,-9.4) 98(-1.54,-9.4) 99(1.54,-9.8) 100(-1.54,-9.8)
  L1 lines w0.2: 1.1,-11.4 1.6,-11.4 1.6,-10.9 ; -1.1,-11.4 -1.6,-11.4 -1.6,-10.9 ; 1.6,10.9 1.6,11.4 1.1,11.4 ; -1.6,10.9 -1.6,11.4 -1.1,11.4
  silkscreen extent -1.6,-11.4 1.6,11.4, body extent -1.69,-11.3 1.69,11.3, height 1.45
"DRC (S-PVSON-N10)" [mm] "Creator MM"
  rect 0.85x0.28 smd mask+0.025: 1(-1.475,1) 2(-1.475,0.5) 3(-1.475,0) 4(-1.475,-0.5) 5(-1.475,-1) 6(1.475,-1) 7(1.475,-0.5) 8(1.475,0) 9(1.475,0.5) 10(1.475,1)
  rect 1.65x2.35 smd paste-1.524 mask+0.025: 11(0,0)
  rect 0.28x0.7 smd mask+0.11: 12(-0.25,1.651) 13(0.25,1.651) 14(0.25,-1.651) 15(-0.25,-1.651)
  silkscreen extent -1.9,-1.65 1.65,2.2, body extent -1.65,-1.65 1.65,1.65, height 1
"DSJ (R-PVSON-N14)" [mm] "Creator MM"
  oval 0.85x0.24 smd mask+0.07: 1(-1.475,1.5) 2(-1.475,1) 3(-1.475,0.5) 4(-1.475,0) 5(-1.475,-0.5) 6(-1.475,-1) 7(-1.475,-1.5) 8(1.475,-1.5) 9(1.475,-1) 10(1.475,-0.5) 11(1.475,0) 12(1.475,0.5) 13(1.475,1) 14(1.475,1.5)
  rect 1.58x2.85 smd paste-10 mask+0.07: 15(0,0)
  rect 0.2x0.65 smd mask+0.07: 16(-0.69,1.875) 17(-0.23,1.875) 18(0.23,1.875) 19(0.69,1.875) 20(0.69,-1.875) 21(0.23,-1.875) 22(-0.23,-1.875) 23(-0.69,-1.875)
  silkscreen extent -2.1,-2.1 1.6,2.1, body extent -1.61,-2.11 1.6,2.1, height 1.04
FID_40X120D [mil]
  round 40 smd paste-40 mask+40: 1(0,0)
FSMRA2JH [mm] "Creator MM"
  round 1.8 hole 1: 1(-2.25,-1.245) 2(2.25,-1.245)
  round 2.2 hole 1.3: 3(-3.505,1.245) 4(3.505,1.245)
  silkscreen extent -3.65,-5.14 3.65,2.85, body extent -4.2,-5.09 4.2,2.77, height 7.05
FSMRA3JH [mm] "Creator MM"
  round 1.8 hole 1: 1(-2.25,-1.245) 2(2.25,-1.245)
  round 2.2 hole 1.3: 3(-3.505,1.245) 4(3.505,1.245)
  silkscreen extent -3.65,-7.14 3.65,2.85, body extent -4.2,-7.1 4.2,2.74, height 7.05
H5007NL [mil]
  rect 75x30 smd: 1(-287.5,275) 2(-287.5,225) 3(-287.5,175) 4(-287.5,125) 5(-287.5,75) 6(-287.5,25) 7(-287.5,-25) 8(-287.5,-75) 9(-287.5,-125) 10(-287.5,-175) 11(-287.5,-225) 12(-287.5,-275) 13(287.5,-275) 14(287.5,-225) 15(287.5,-175) 16(287.5,-125) 17(287.5,-75) 18(287.5,-25) 19(287.5,25) 20(287.5,75) 21(287.5,125) 22(287.5,175) 23(287.5,225) 24(287.5,275)
  silkscreen extent -240,-346 240,346, body extent -240,-346 240,346, height 217
"HDMI V1.1" [mm] "Changed holes to slots"
  rect 2.6x0.3 smd mask+0.025: 1(-3.36,4.5) 2(-3.36,4) 3(-3.36,3.5) 4(-3.36,3) 5(-3.36,2.5) 6(-3.36,2) 7(-3.36,1.5) 8(-3.36,1) 9(-3.36,0.5) 10(-3.36,0) 11(-3.36,-0.5) 12(-3.36,-1) 13(-3.36,-1.5) 14(-3.36,-2) 15(-3.36,-2.5) 16(-3.36,-3) 17(-3.36,-3.5) 18(-3.36,-4) 19(-3.36,-4.5)
  oval 3.7x1.7 hole 0.9 slot 2.7 at 0 deg: MTG1(-2.6,7.25) MTG3(-2.6,-7.25)
  oval 2.7x1.7 hole 0.9 slot 1.7 at 0 deg: MTG2(3.36,7.25) MTG4(3.36,-7.25)
  silkscreen extent -5.1,-10 12.05,10, body extent -4.2,-7.5 7.95,7.5, height 6.28
HDR_1x2_2.54MM [mm]
  rect 2x1.6 hole 1.1: 1(0,0)
  oval 2x1.6 hole 1.1: 2(0,-2.54)
  silkscreen extent -1.3,-3.81 1.3,1.27, body extent -1.2,-3.62 1.2,1.06, height 8.4
HDR_1X2_2.54MM_MOLEX_KK [mm] "Creator MM"
  rect 1.6x2 hole 1.1: 1(0,0)
  oval 1.6x2 hole 1.1: 2(2.54,0)
  silkscreen extent -1.33,-3.4 3.87,3.2, body extent -1.19,-3.28 3.73,3.07, height 10.69
Hdr_1x6_2.54mm [mm] "Creator MM"
  rect 2x1.6 hole 1.1: 1(0,0)
  oval 2x1.6 hole 1.1: 2(0,-2.54) 3(0,-5.08) 4(0,-7.62) 5(0,-10.16) 6(0,-12.7)
  silkscreen extent -1.3,-13.97 1.3,1.27, body extent -1.2,-13.77 1.2,1.07, height 8.4
HDR_2x5_2.54mm_BOXED [mm] "Creator MM"
  rect 1.7x1.7 hole 1: 1(0,0)
  round 1.7 hole 1: 2(2.54,0) 3(0,-2.54) 4(2.54,-2.54) 5(0,-5.08) 6(2.54,-5.08) 7(0,-7.62) 8(2.54,-7.62) 9(0,-10.16) 10(2.54,-10.16)
  silkscreen extent -2.9,-15.19 5.89,5.03, body extent -2.91,-15.22 5.91,5.08, height 8.89
HDR_2x7_2.54MM_BOXED [mm] "Creator MM"
  rect 1.7x1.7 hole 1: 1(0,0)
  round 1.7 hole 1: 2(2.54,0) 3(0,-2.54) 4(2.54,-2.54) 5(0,-5.08) 6(2.54,-5.08) 7(0,-7.62) 8(2.54,-7.62) 9(0,-10.16) 10(2.54,-10.16) 11(0,-12.7) 12(2.54,-12.7) 13(0,-15.24) 14(2.54,-15.24)
  silkscreen extent -2.9,-20.27 5.89,5.03, body extent -2.91,-20.31 5.9,5.06, height 8.89
IHLP_204MILX216MIL [mm] "Creator MM"
  rect 2.115x2.79 smd: 1(-2.137,0) 2(2.138,0)
  silkscreen extent -2.9,-2.7 2.9,2.7, body extent -2.75,-2.6 2.75,2.6, height 3
"iMX6 TinyRex Module 3D" [mil] "For 1.5mm standoff mating. .Creator MM"
  body extent 0,0 1496,1496, height 199
LED_0603 [mm]
  rect 0.8x0.8 smd: 1(-0.8,0) 2(0.8,0)
  silkscreen extent -1.78,-0.76 1.52,0.76, body extent -0.85,-0.4 0.85,0.4, height 0.66
MH_5.2MMD_2.7MMD [mm] "Creator MM"
  round 5.2 / inner round 3.683 / far side round 5.2 hole 2.7: 1(0,0)
MH_5MMD_2MMD [mm]
  round 5 / inner round 3.683 / far side round 5 hole 2: 1(0,0)
MH_7.4MMD_3.2MMD [mm]
  round 7.4 / inner round 3.683 / far side round 7.4 hole 3.2 mask+0.025: 1(0,0)
MICRO_HDMI [mm] "Creator MM"
  rect 0.2x0.85 smd mask+0.03: 1(1.8,6.475) 3(1.4,6.475) 5(1,6.475) 7(0.6,6.475) 9(0.2,6.475) 11(-0.2,6.475) 13(-0.6,6.475) 15(-1,6.475) 17(-1.4,6.475) 19(-1.8,6.475)
  rect 0.2x1 smd mask+0.03: 2(1.6,5.25) 4(1.2,5.25) 6(0.8,5.25) 8(0.4,5.25) 10(0,5.25) 12(-0.4,5.25) 14(-0.8,5.25) 16(-1.2,5.25) 18(-1.6,5.25)
  oval 1.5x2.55 hole 0.65 slot 1.7 at 90 deg: MTG1(3.1,5.06) MTG2(-3.1,5.06) MTG3(3.1,1.7) MTG4(-3.1,1.7)
  silkscreen extent -5.5,-2.9 5.5,6.9, body extent -3.25,-0.7 3.25,6.8, height 2.97
Micro_SD_card [mil] ".Creator MM"
  body extent -341,-541 93,50, height 72
MINI_PCIE_52PIN_CARD_CON [mm] "Creator MM"
  rect 2x0.6 smd mask+0.05: 1(-4.1,-0.7) 2(4.1,-1.1) 3(-4.1,-1.5) 4(4.1,-1.9) 5(-4.1,-2.3) 6(4.1,-2.7) 7(-4.1,-3.1) 8(4.1,-3.5) 9(-4.1,-3.9) 10(4.1,-4.3) 11(-4.1,-4.7) 12(4.1,-5.1) 13(-4.1,-5.5) 14(4.1,-5.9) 15(-4.1,-6.3) 16(4.1,-6.7) 17(-4.1,-10.3) 18(4.1,-10.7) 19(-4.1,-11.1) 20(4.1,-11.5) 21(-4.1,-11.9) 22(4.1,-12.3) 23(-4.1,-12.7) 24(4.1,-13.1) 25(-4.1,-13.5) 26(4.1,-13.9) 27(-4.1,-14.3) 28(4.1,-14.7) 29(-4.1,-15.1) 30(4.1,-15.5) 31(-4.1,-15.9) 32(4.1,-16.3) 33(-4.1,-16.7) 34(4.1,-17.1) 35(-4.1,-17.5) 36(4.1,-17.9) 37(-4.1,-18.3) 38(4.1,-18.7) 39(-4.1,-19.1) 40(4.1,-19.5) 41(-4.1,-19.9) 42(4.1,-20.3) 43(-4.1,-20.7) 44(4.1,-21.1) 45(-4.1,-21.5) 46(4.1,-21.9) 47(-4.1,-22.3) 48(4.1,-22.7) 49(-4.1,-23.1) 50(4.1,-23.5) 51(-4.1,-23.9) 52(4.1,-24.3)
  rect 3.2x2.3 smd: 53(-3.5,2.15) 54(-3.5,-27.15)
  rrect70% 0x0 hole 1.6 unplated: 55(0,0)
  rrect70% 0x0 hole 1.1 unplated: 56(0,-25)
  silkscreen extent -5.1,-26.8 5.1,1.8, body extent -5,-27.35 5,2.35, height 5.95
MINI_PCIE_52PIN_CARD_LATCH [mm] "Creator MM"
  rect 2.7x1.2 smd: 1(-2.45,-2.05) 2(-2.45,-4.55) 4(-2.45,-26.25) 5(-2.45,-28.75)
  rect 1.9x1.5 smd: 3(3.45,-3.3) 6(3.45,-27.5)
  rrect70% 0x0 hole 1.55: 7(0.7,-3.3)
  rrect70% 0x0 hole 1.05: 8(0.7,-27.5)
  silkscreen extent -2.65,-29.9 4.65,-0.9, body extent -3.25,-29.9 4.65,-0.9, height 6.7
"MINI_PCIE_FULL CARD" [mil] ".Creator MM"
  body extent 0,0 2006,1181, height 272
"NUT A4 SS M2" [mil] "Creator MM"
  body extent -91,-79 91,79, height 183
POWER_JACK_5.5_2.1MM_NS_V1.1 [mm] "Creator MM. v1.1 - changed holes for slots"
  oval 5x4 hole 1 slot 3.7 at 0 deg: 1(0,0)
  oval 5x4 hole 1 slot 3.2 at 0 deg: 2(0,6)
  oval 4x5 hole 1 slot 3.2 at 90 deg: 3(-4.7,3)
  silkscreen extent -4.65,-0.85 4.65,19.85, body extent -4.9,-0.7 4.5,13.7, height 11.02
R0402 [mm]
  rect 0.5x0.6 smd: 1(-0.5,0) 2(0.5,0)
  silkscreen extent -1,-0.6 1,0.6, body extent -0.5,-0.25 0.5,0.25, height 0.4
R1206 [mm]
  rect 0.9x1.6 smd: 1(-1.45,0) 2(1.45,0)
  silkscreen extent -2.16,-1.14 2.16,1.14, body extent -1.6,-0.8 1.6,0.8, height 0.84
RJ45LED [mm]
  round 1.3 hole 0.9: 1(2.03,3.55) 2(0.25,2.53) 3(2.03,1.52) 4(0.25,0.5) 5(2.03,-0.51) 6(0.25,-1.52) 7(2.03,-2.54) 8(0.25,-3.56)
  round 1.575 hole 0.9: 9(-4.57,6.86) 10(-4.57,4.57) 11(-4.57,-4.57) 12(-4.57,-6.86)
  round 2.7 hole 1.6: 13(1.14,8.13) 14(1.14,-8.13)
  round 3.25 hole 3.25 unplated: 15(4.57,6.35) 16(4.57,-6.35)
  silkscreen extent -5.91,-8.3 16.6,8.3, body extent -5.9,-9.3 10.82,9.33, height 14.8
"RSE (R-PUQFN-N10)" [mm] "Creator MM"
  rect 0.58x0.3 smd mask+0.03: 1(-0.64,0.75) 4(-0.64,-0.75) 6(0.64,-0.75) 9(0.64,0.75)
  rect 0.58x0.25 smd mask+0.03: 2(-0.64,0.25) 3(-0.64,-0.25) 7(0.64,-0.25) 8(0.64,0.25)
  rect 0.3x0.63 smd mask+0.03: 5(0,-0.86) 10(0,0.86)
  silkscreen extent -1.17,-1.15 0.8,1.57, body extent -0.75,-1 0.75,1, height 0.6
SATA_VERTICAL [mm]
  round 1.3 hole 0.74: 1(0,0) 4(-3.81,0) 7(-7.62,0)
  oval 1.07x1.3 hole 0.74: 2(-1.27,1) 3(-2.54,1) 5(-5.08,1) 6(-6.35,1)
  round 2 hole 1.35: 8(2.67,0.5) 9(-10.29,0.5)
  silkscreen extent -12.51,-2.6 4.49,3.9, body extent -12.43,-2.55 4.47,3.9, height 8.43
SC70_5 [mm]
  rect 0.75x0.4 smd mask+0.025: 1(-0.95,0.65) 2(-0.95,0) 3(-0.95,-0.65) 4(0.95,-0.65) 5(0.95,0.65)
  silkscreen extent -0.76,-1.14 0.76,1.14, body extent -1.21,-1.14 1.21,1.14, height 1.1
SC70_SOT323 [mm]
  rect 0.9x0.7 smd: 1(-0.95,0.65) 2(-0.95,-0.65) 3(0.95,0)
  silkscreen extent -0.7,-1.27 0.7,1.27, body extent -1.27,-1.27 1.27,1.27, height 1.1
"SCREW M2x8" [mil] "Creator MM"
  body extent -91,-79 91,79, height 252
SOD323 [mil]
  rect 22x27 smd mask+3: 1(-48,0) 2(48,0)
  silkscreen extent -75,-28 71,28, body extent -49,-25 49,25, height 39
SOD-123FL [mm] "Wider inside part of pads. Creator MM"
  rect 1.25x1.22 smd: 1(-1.475,0) 2(1.475,0)
  silkscreen extent -2.5,-0.9 2.4,0.9, body extent -1.8,-0.82 1.8,0.83, height 0.95
SOT143 [mm]
  rect 0.9x1.2 smd: 1(-1,0.8)
  rect 0.9x0.8 smd: 2(-1,-1) 3(1,-1) 4(1,1)
  silkscreen extent -1,-1.7 1,1.7, body extent -1,-1.7 1,1.7, height 1
SOT363 [mm] "Creator MM Used Diodes land pattern as suggested"
  rect 0.8x0.42 smd mask+0.06: 1(-0.95,0.65) 2(-0.95,0) 3(-0.95,-0.65) 4(0.95,-0.65) 5(0.95,0) 6(0.95,0.65)
  silkscreen extent -1.4,-1.2 0.7,1.4, body extent -1.2,-1.1 1.2,1.1, height 1.1
SOT-23-3-123 [mm]
  rect 0.9x0.8 smd: 1(-1,0.95) 2(-1,-0.95) 3(1,0)
  silkscreen extent -0.76,-1.65 0.76,1.65, body extent -1.27,-1.65 1.27,1.65, height 1.1
"SPACER 2.5/4.5X1.5MM" [mil] "Creator MM"
  body extent -89,-89 88,88, height 59
"TO-277A (SMPC)" [mm] "Creator MM"
  rect 1.6x1.7 smd: 1(1.065,-2.865) 2(-1.065,-2.865)
  rect 5.2x5.2 smd paste-10: 3(0,1.04)
  silkscreen extent -2.3,-3.2 2.3,-1.9, body extent -2.37,-3.35 2.38,3.3, height 1.2
TP_25C [mil]
  round 25 smd paste-25 mask+2: 1(0,0)
TSSOP_38 [mm]
  rect 1.4x0.28 smd mask+0.025: 1(-2.85,4.5) 2(-2.85,4) 3(-2.85,3.5) 4(-2.85,3) 5(-2.85,2.5) 6(-2.85,2) 7(-2.85,1.5) 8(-2.85,1) 9(-2.85,0.5) 10(-2.85,0) 11(-2.85,-0.5) 12(-2.85,-1) 13(-2.85,-1.5) 14(-2.85,-2) 15(-2.85,-2.5) 16(-2.85,-3) 17(-2.85,-3.5) 18(-2.85,-4) 19(-2.85,-4.5) 20(2.85,-4.5) 21(2.85,-4) 22(2.85,-3.5) 23(2.85,-3) 24(2.85,-2.5) 25(2.85,-2) 26(2.85,-1.5) 27(2.85,-1) 28(2.85,-0.5) 29(2.85,0) 30(2.85,0.5) 31(2.85,1) 32(2.85,1.5) 33(2.85,2) 34(2.85,2.5) 35(2.85,3) 36(2.85,3.5) 37(2.85,4) 38(2.85,4.5)
  silkscreen extent -4,-5 2.3,5, body extent -2.3,-5 2.3,5, height 1.2
USB-2A [mm] "Creator MM"
  round 1.524 hole 1: 1(3.5,0.13) 2(1,0.13) 3(-1,0.13) 4(-3.5,0.13) 5(3.5,-2.49) 6(1,-2.49) 7(-1,-2.49) 8(-3.5,-2.49)
  round 3 hole 2.4: 9(-6.57,2.84) 10(6.57,2.84) 11(-6.57,-2.84) 12(6.57,-2.84)
  silkscreen extent -10.75,-4.5 10.75,18.4, body extent -8.1,-4.1 8.14,13.08, height 15.78
USB_MICRO_AB [mm] "Creator MM"
  rect 1.35x0.35 smd mask+0.025: 1(2.675,1.3) 2(2.675,0.65) 3(2.675,0) 4(2.675,-0.65) 5(2.675,-1.3)
  rrect84% 1.25x1.1 hole 0.85 mask+0.04: 6(3,2.225) 7(3,-2.225)
  rrect60% 1.9x2.425 hole 1.3 copper offset 0,-0.363: 8(0,4.175)
  rect 1.9x1.8 smd paste-10: 9(0,1.15) 10(0,-1.15)
  rrect60% 1.9x2.425 hole 1.3 copper offset 0,0.363: 11(0,-4.175)
  silkscreen extent -4.75,-5.4 2.85,5.4, body extent -2.75,-4.32 3.04,4.33, height 2.76
WSON8_6X5MM [mm] "Creator MM"
  rect 0.9x0.45 smd: 1(-2.75,1.905) 2(-2.75,0.635) 3(-2.75,-0.635) 4(-2.75,-1.905) 5(2.75,-1.905) 6(2.75,-0.635) 7(2.75,0.635) 8(2.75,1.905)
  rect 3.4x4 smd: 9(0,0)
  silkscreen extent -3.1,-2.6 3.1,3.1, body extent -3,-2.5 3,2.5, height 0.8
ZIF_RA_BOTTOM_15X1MM [mm] ".Creator MM Added overlay if not moutef properly"
  rect 0.61x2 smd: 1(-7,1.4) 2(-6,1.4) 3(-5,1.4) 4(-4,1.4) 5(-3,1.4) 6(-2,1.4) 7(-1,1.4) 8(0,1.4) 9(1,1.4) 10(2,1.4) 11(3,1.4) 12(4,1.4) 13(5,1.4) 14(6,1.4) 15(7,1.4)
  rect 2.68x3.6 smd: 16(-9.99,-1.4) 17(9.99,-1.4)
  silkscreen extent -11.6,-7 11.6,1.5, body extent -11.46,-5.04 11.46,1.5, height 2.53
